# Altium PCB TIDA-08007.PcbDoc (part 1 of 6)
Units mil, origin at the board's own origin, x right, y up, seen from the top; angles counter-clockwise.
Board outline 4212.6 x 2047.24 mil, 10 copper layers (Top Layer, GND 1, Signal Layer 1, GND 2, Split PWR 1, Split PWR 2, GND 3, Signal Layer 2, GND 4, Bottom Layer), stack 66.4 mil thick; 291 components, 178 nets, 1281 pads, 873 vias.
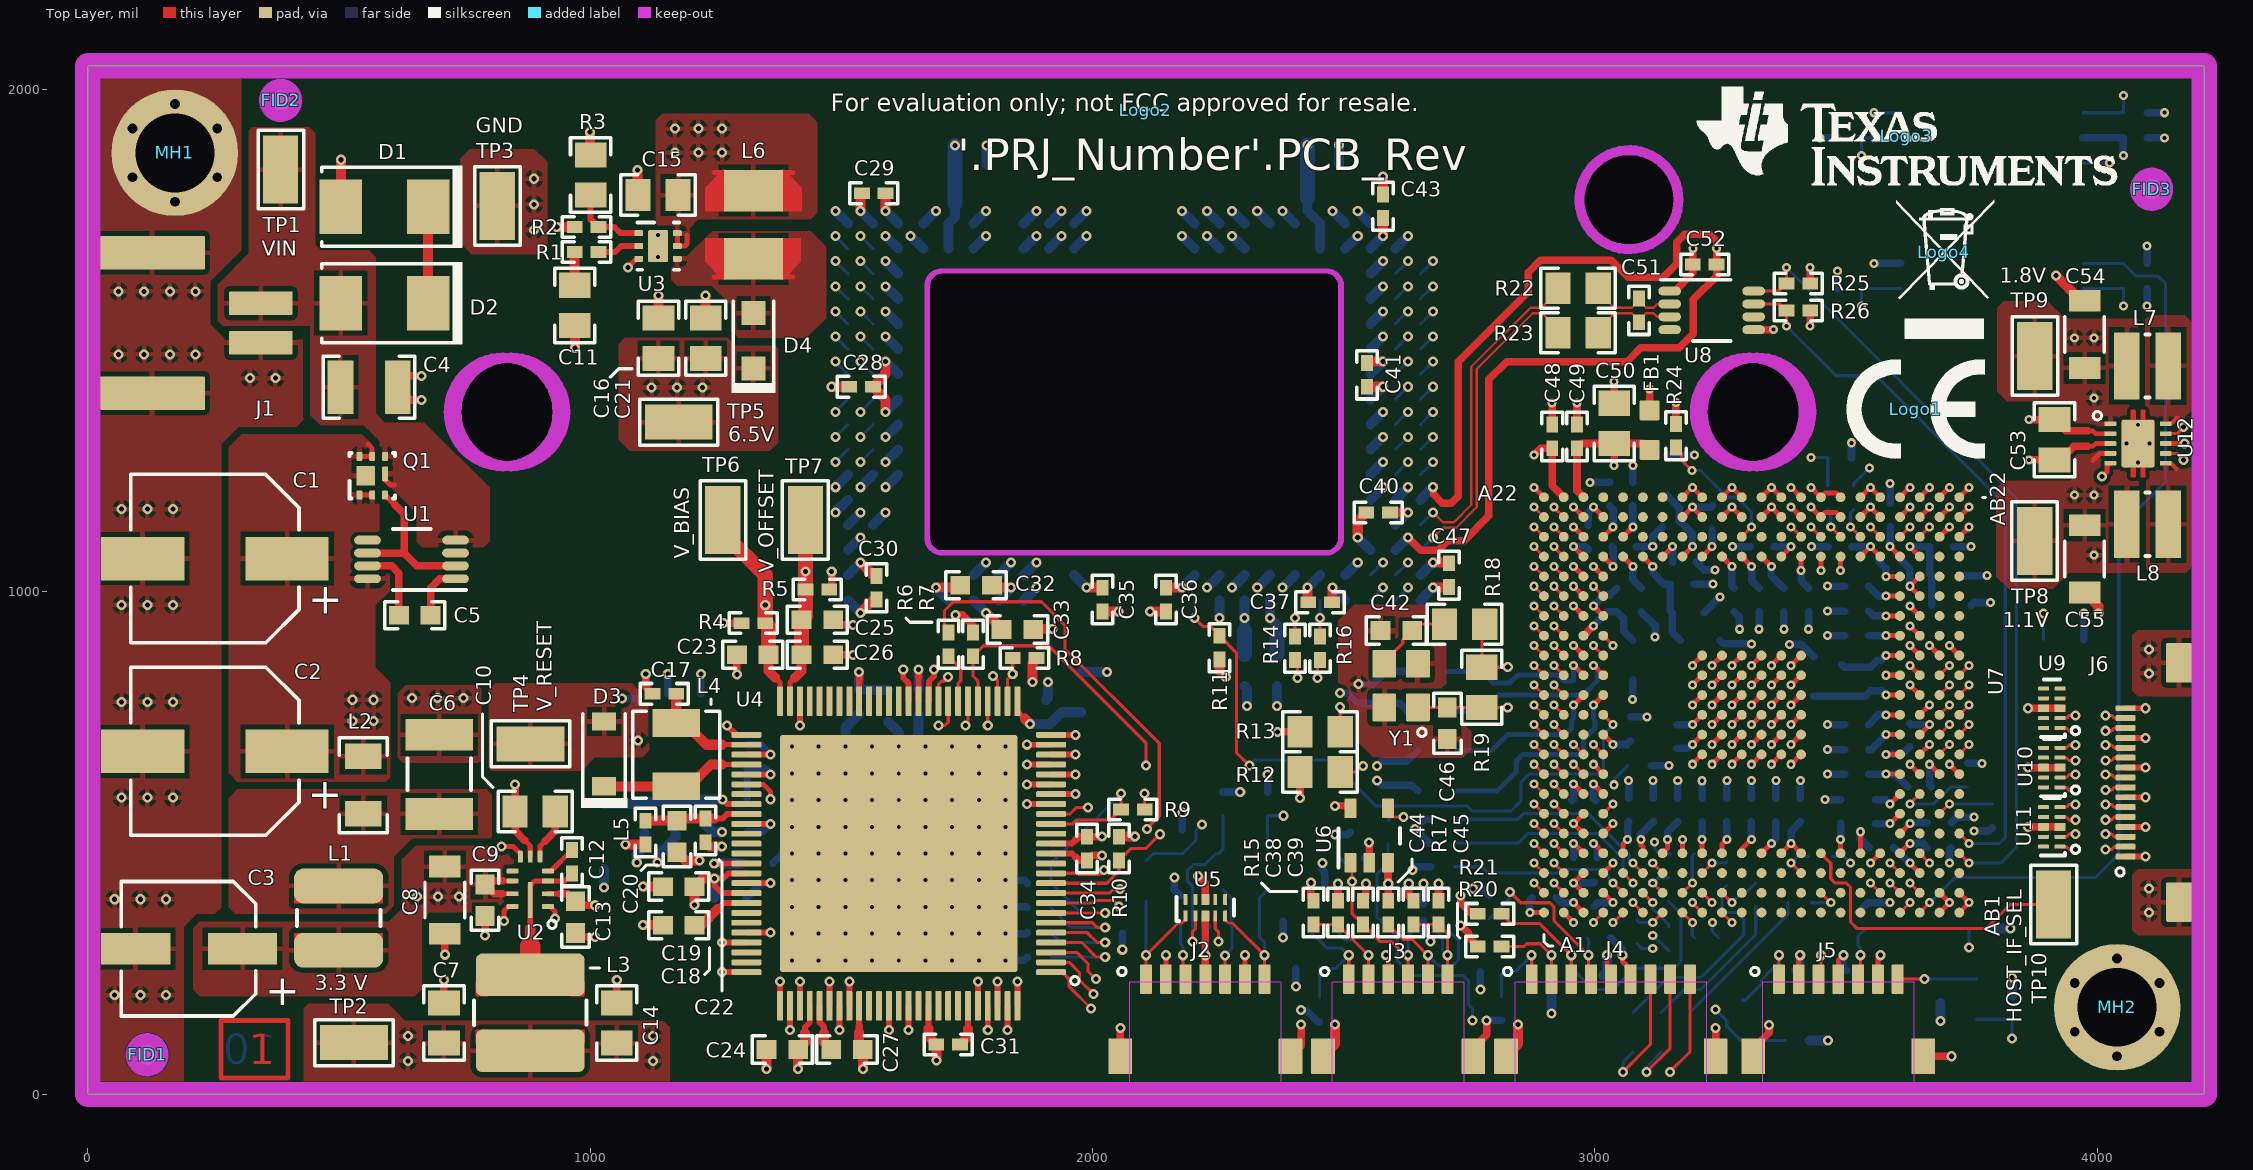
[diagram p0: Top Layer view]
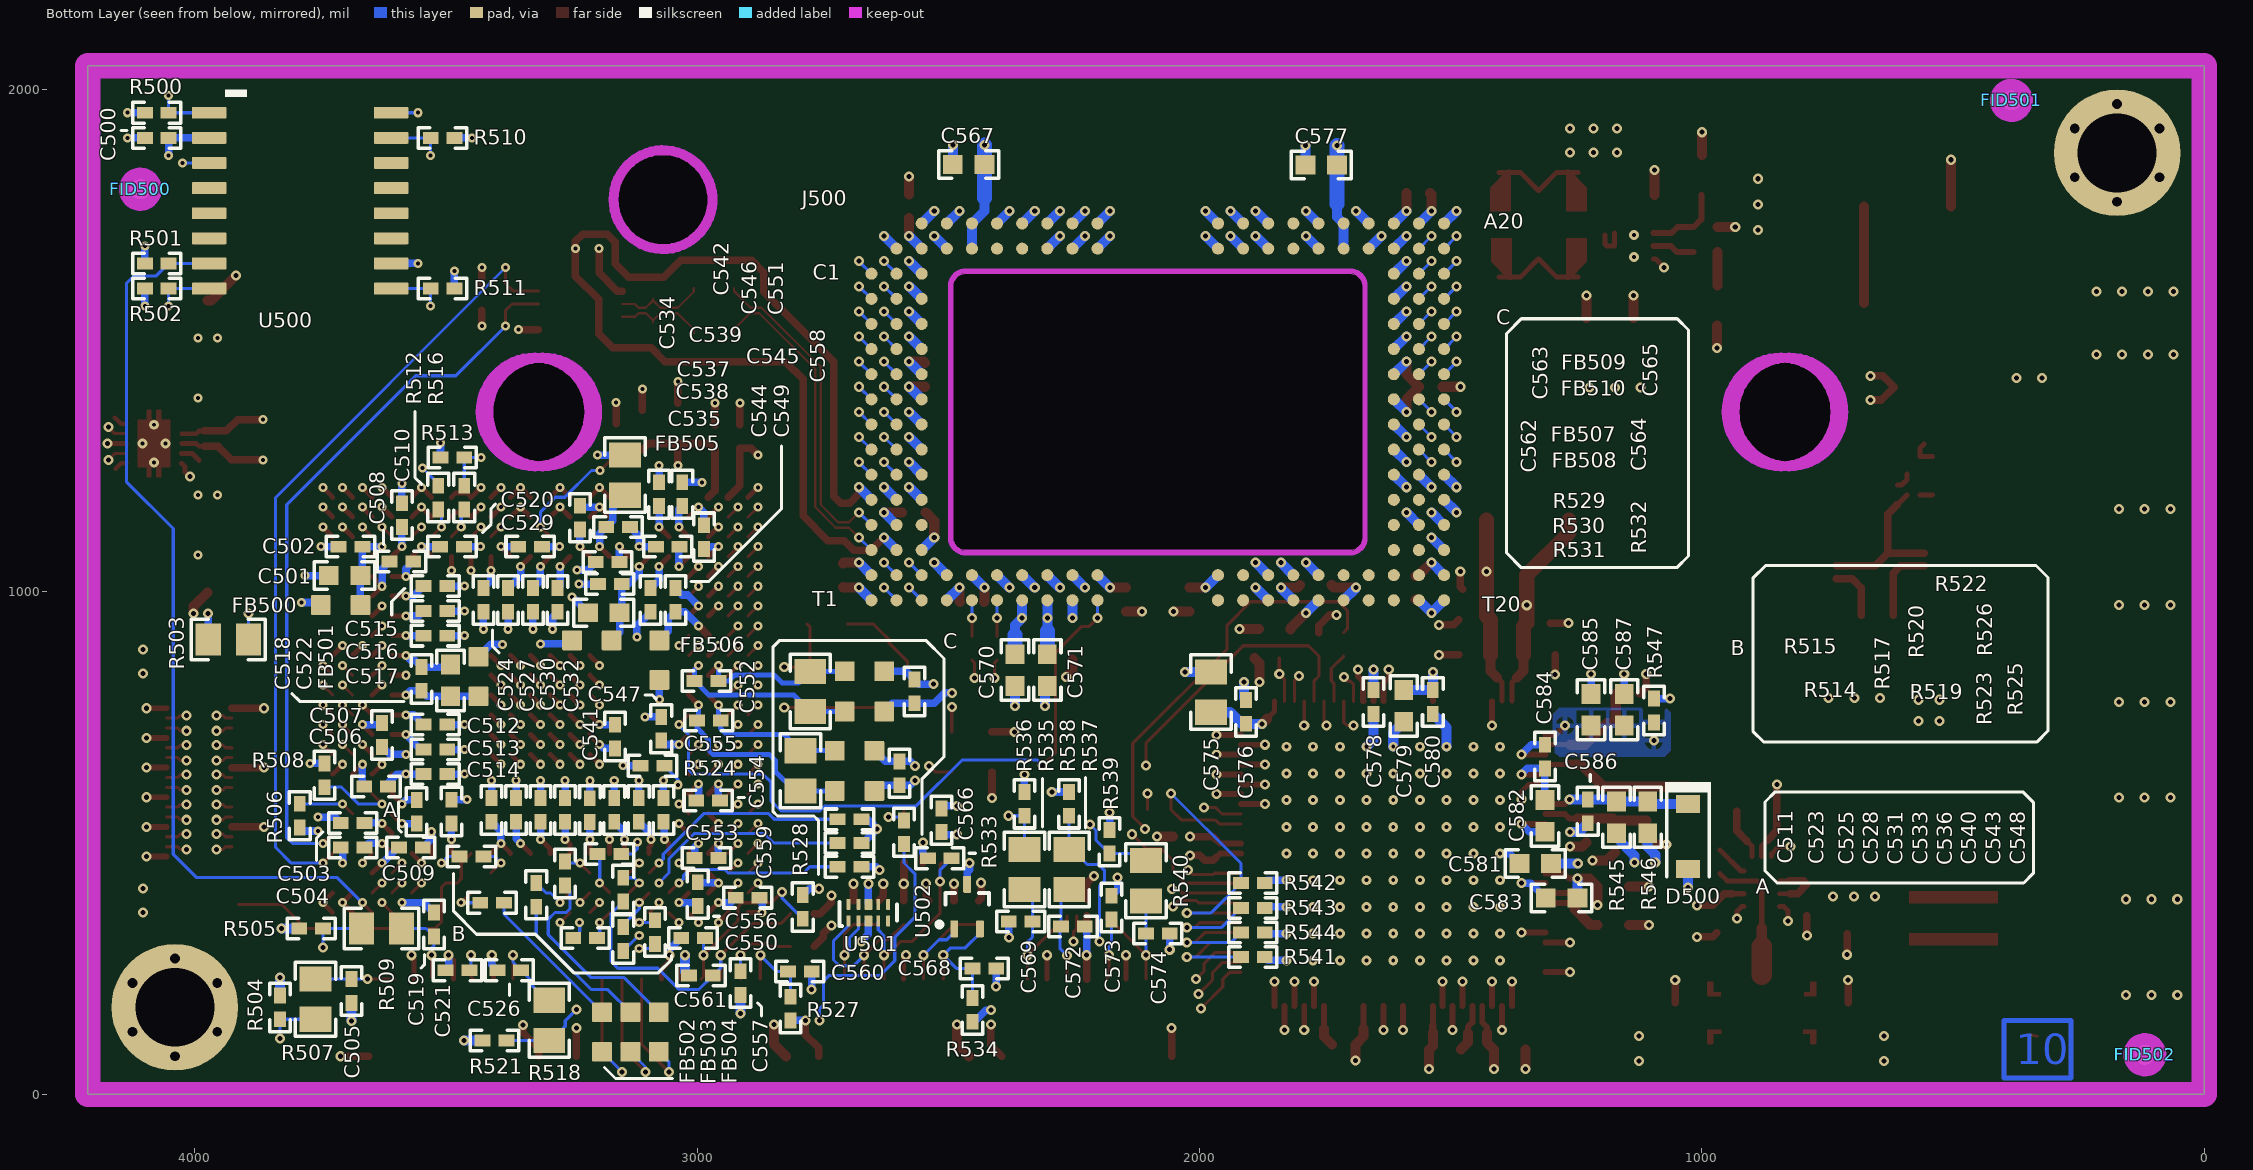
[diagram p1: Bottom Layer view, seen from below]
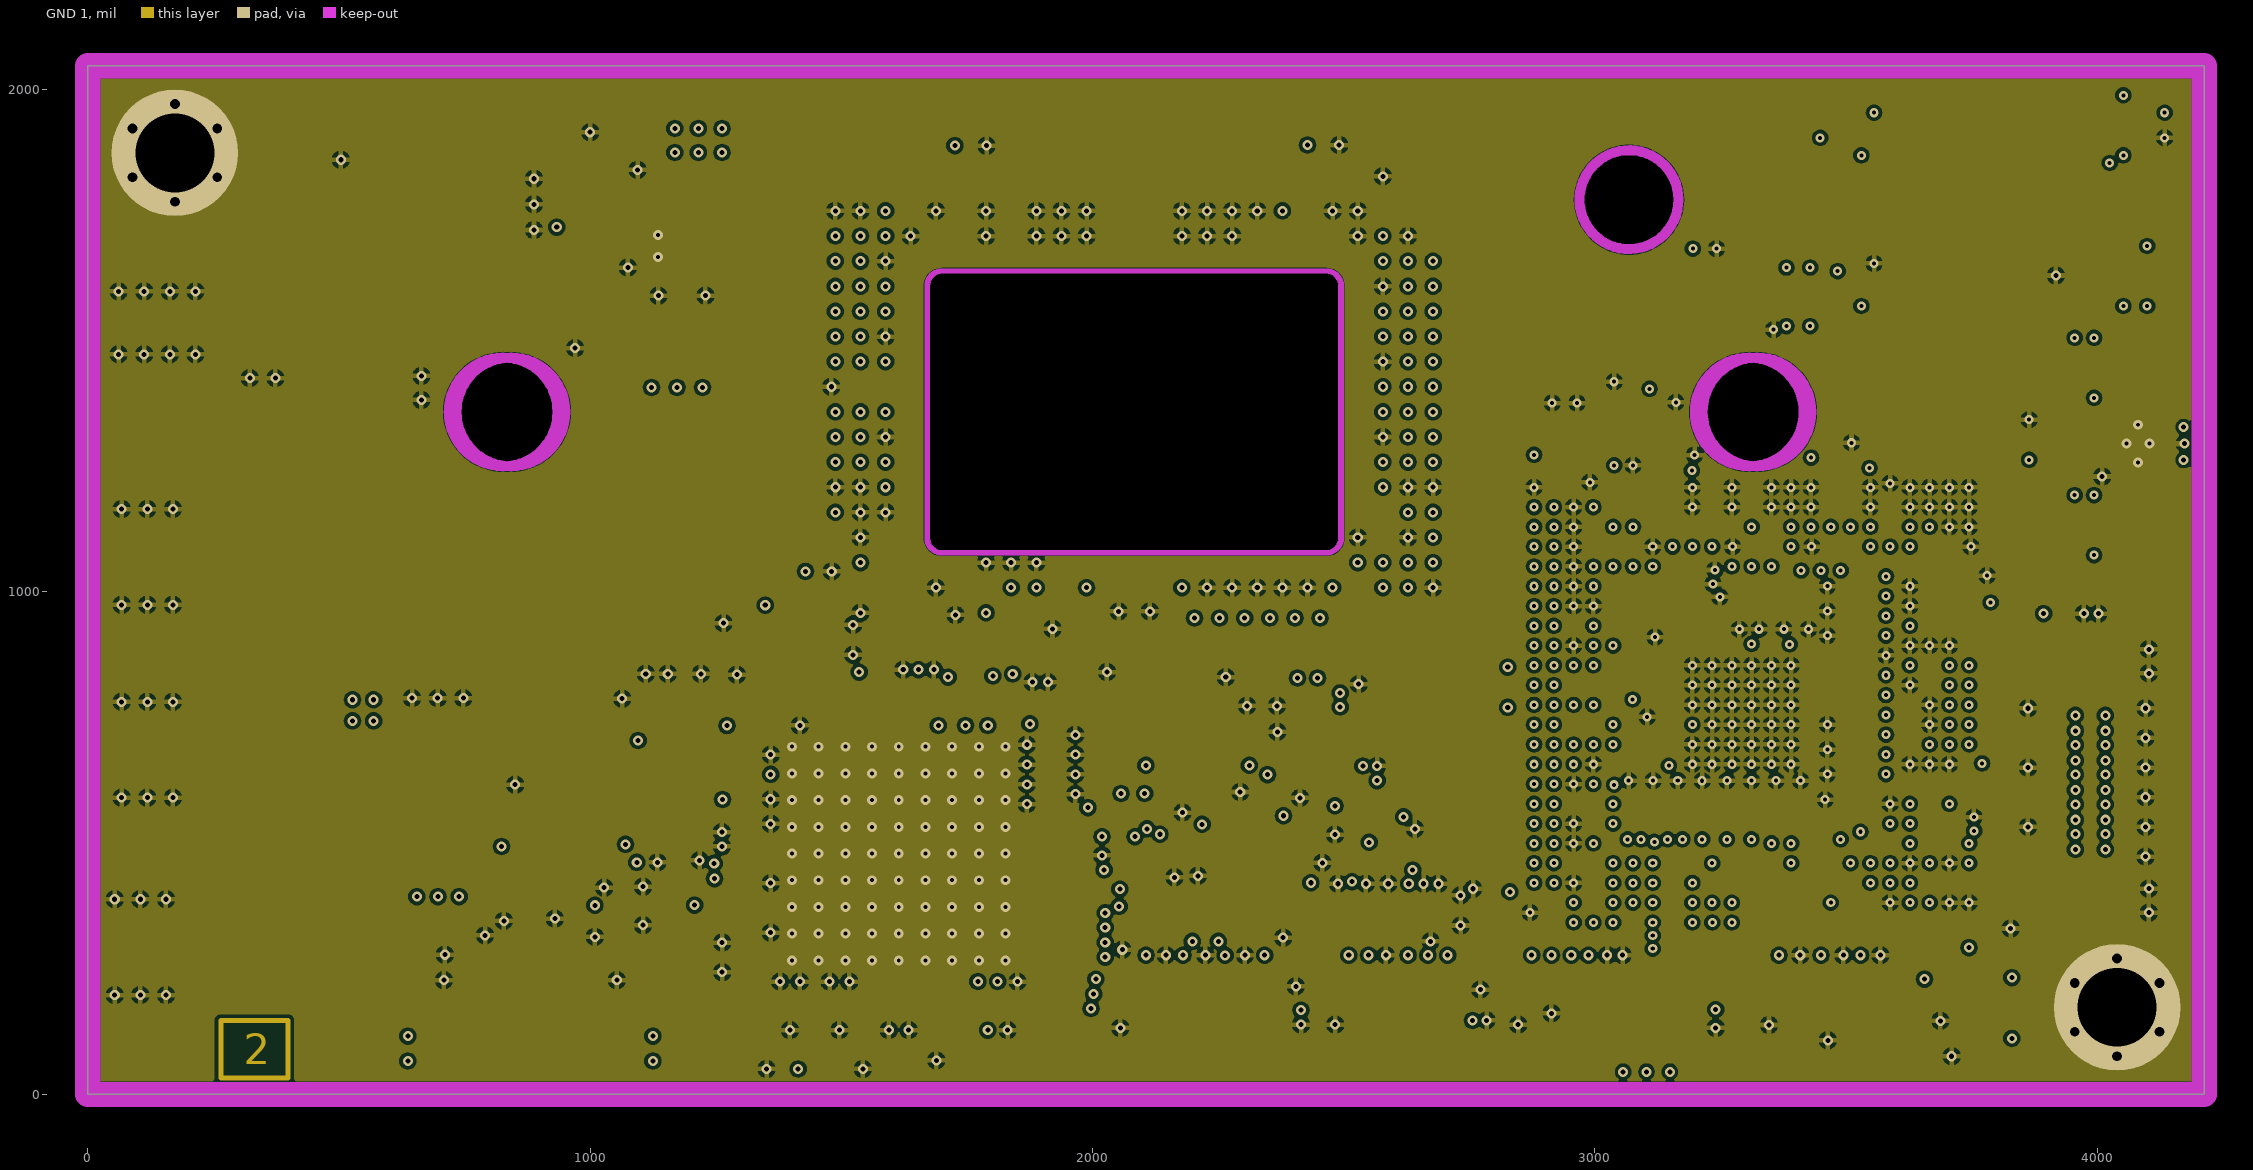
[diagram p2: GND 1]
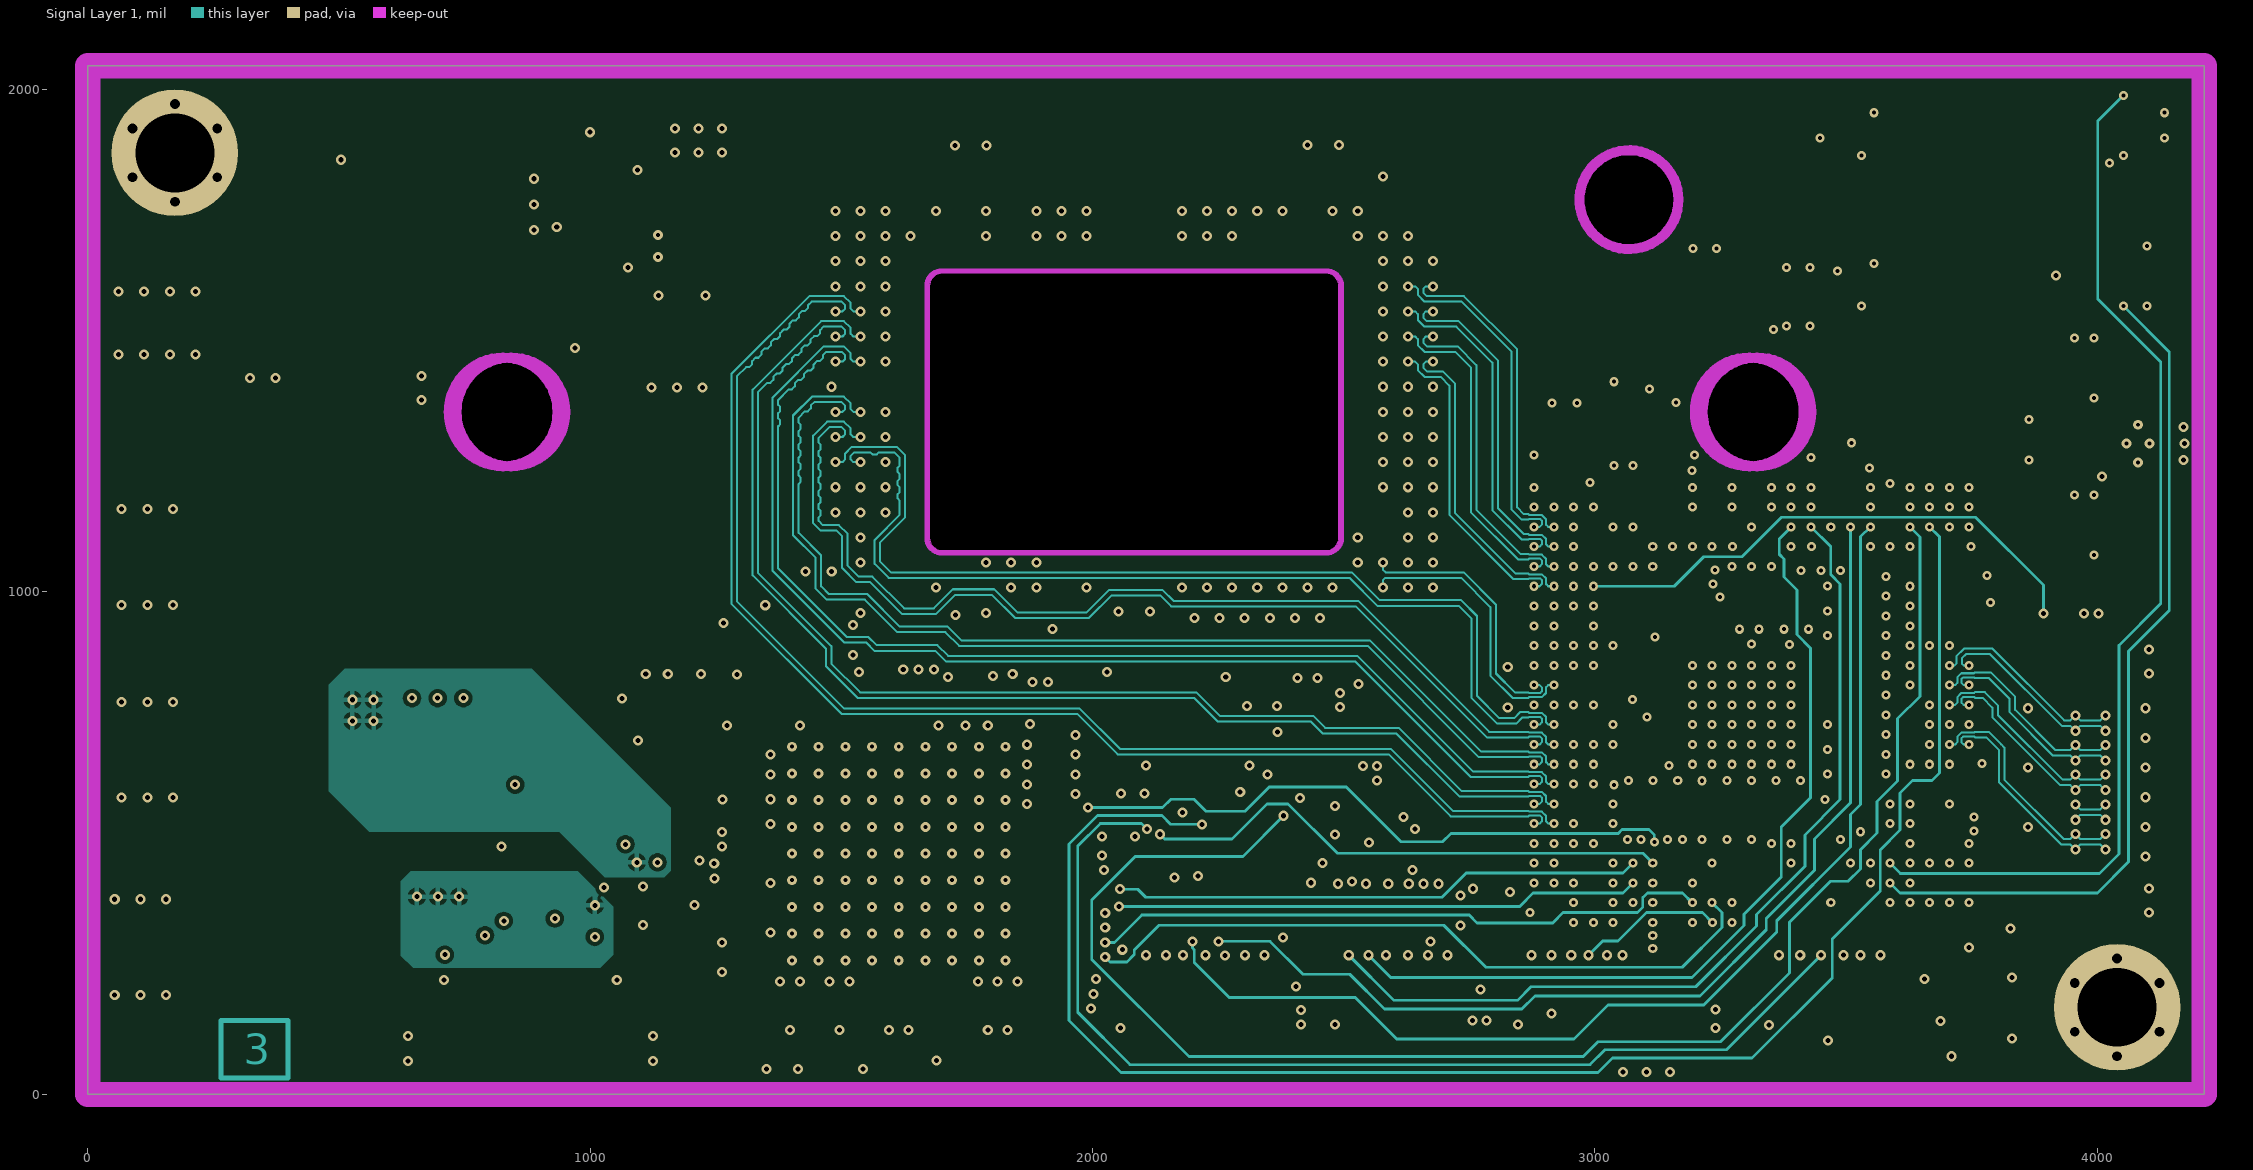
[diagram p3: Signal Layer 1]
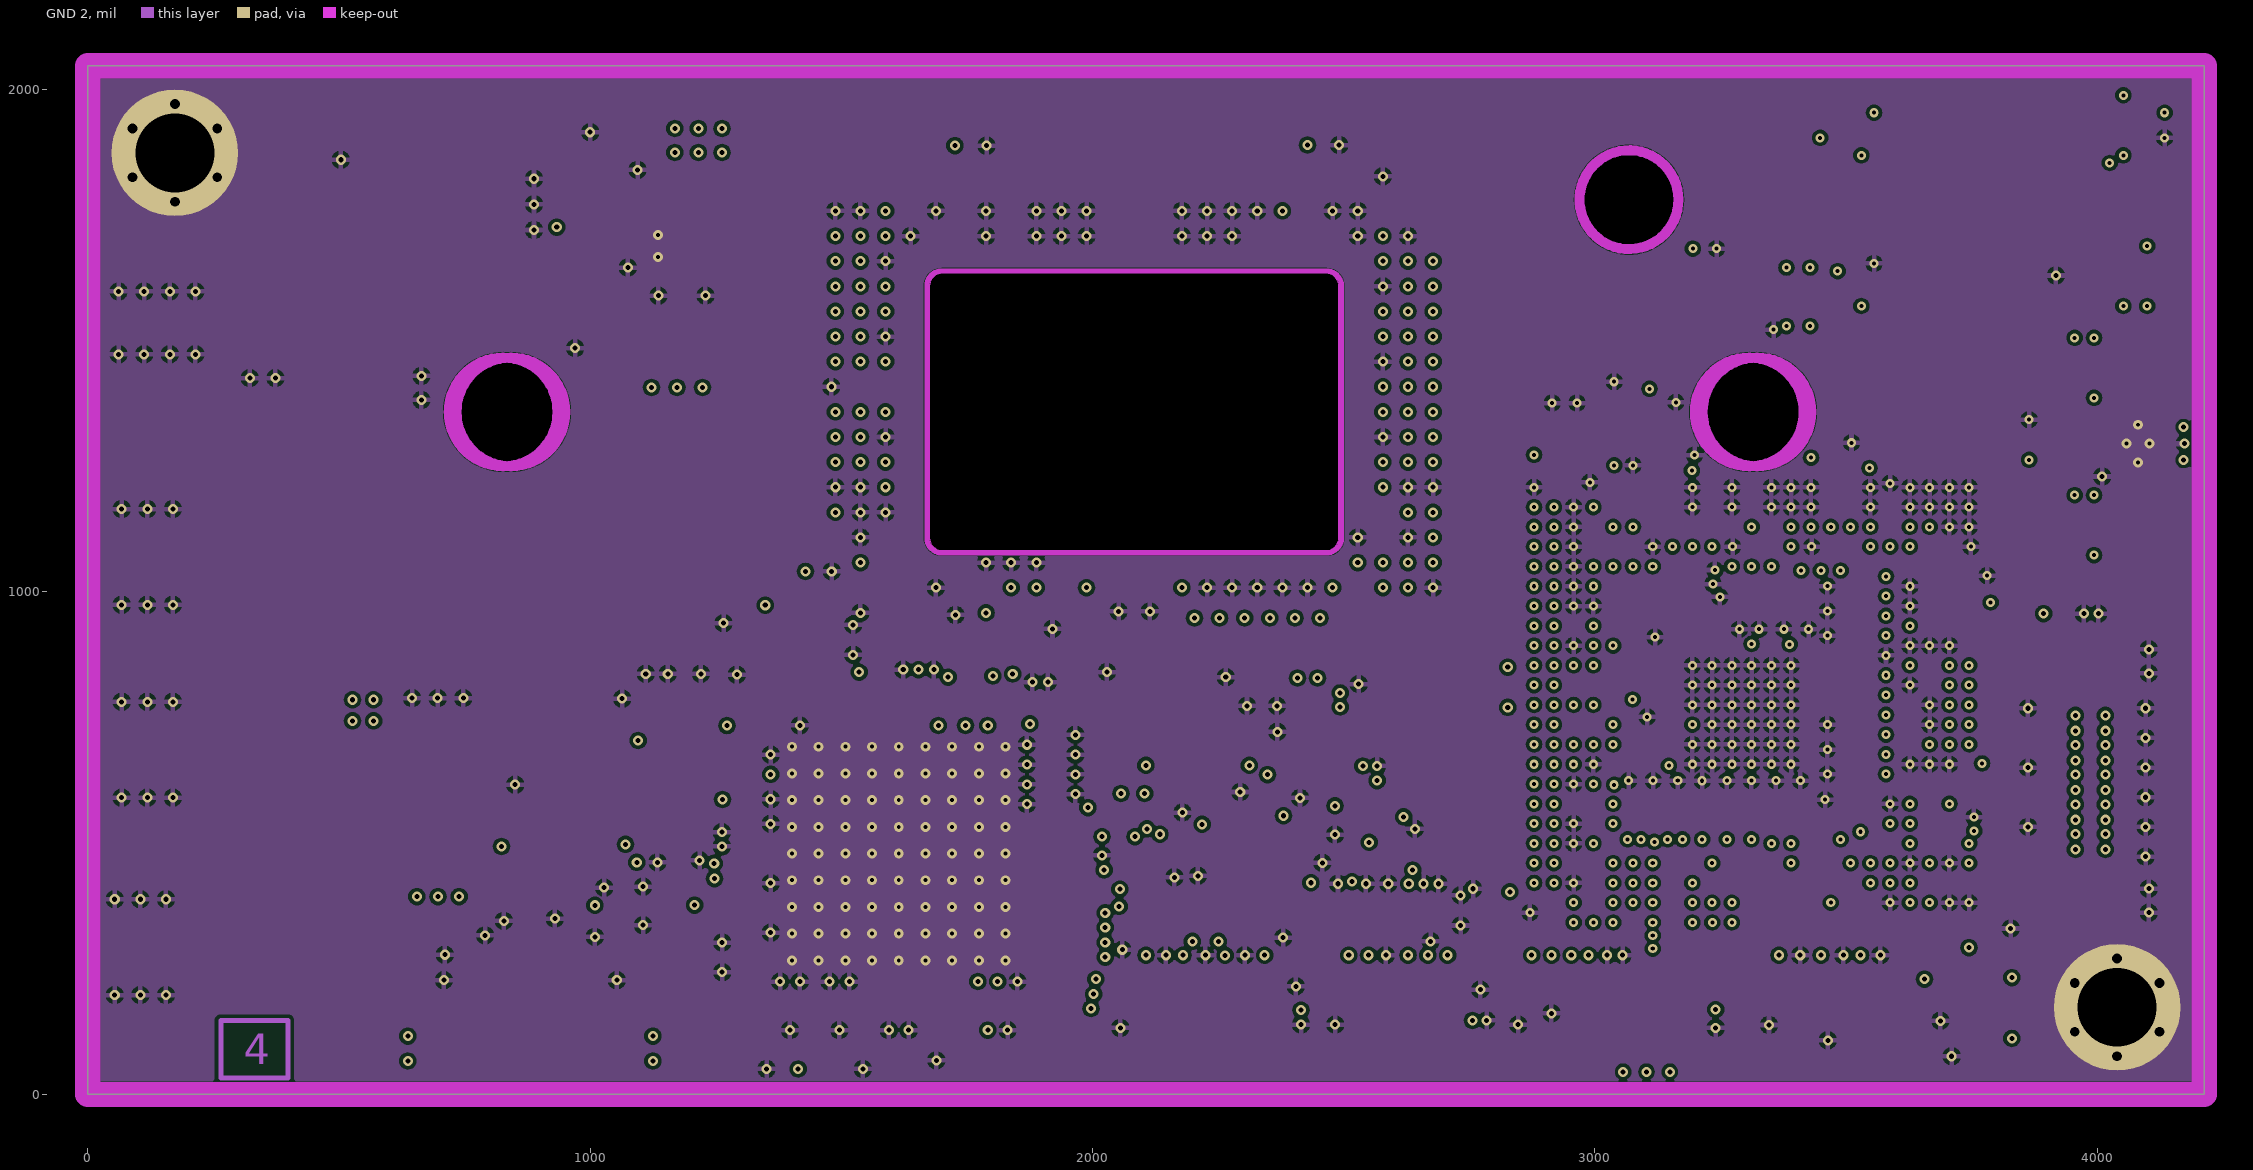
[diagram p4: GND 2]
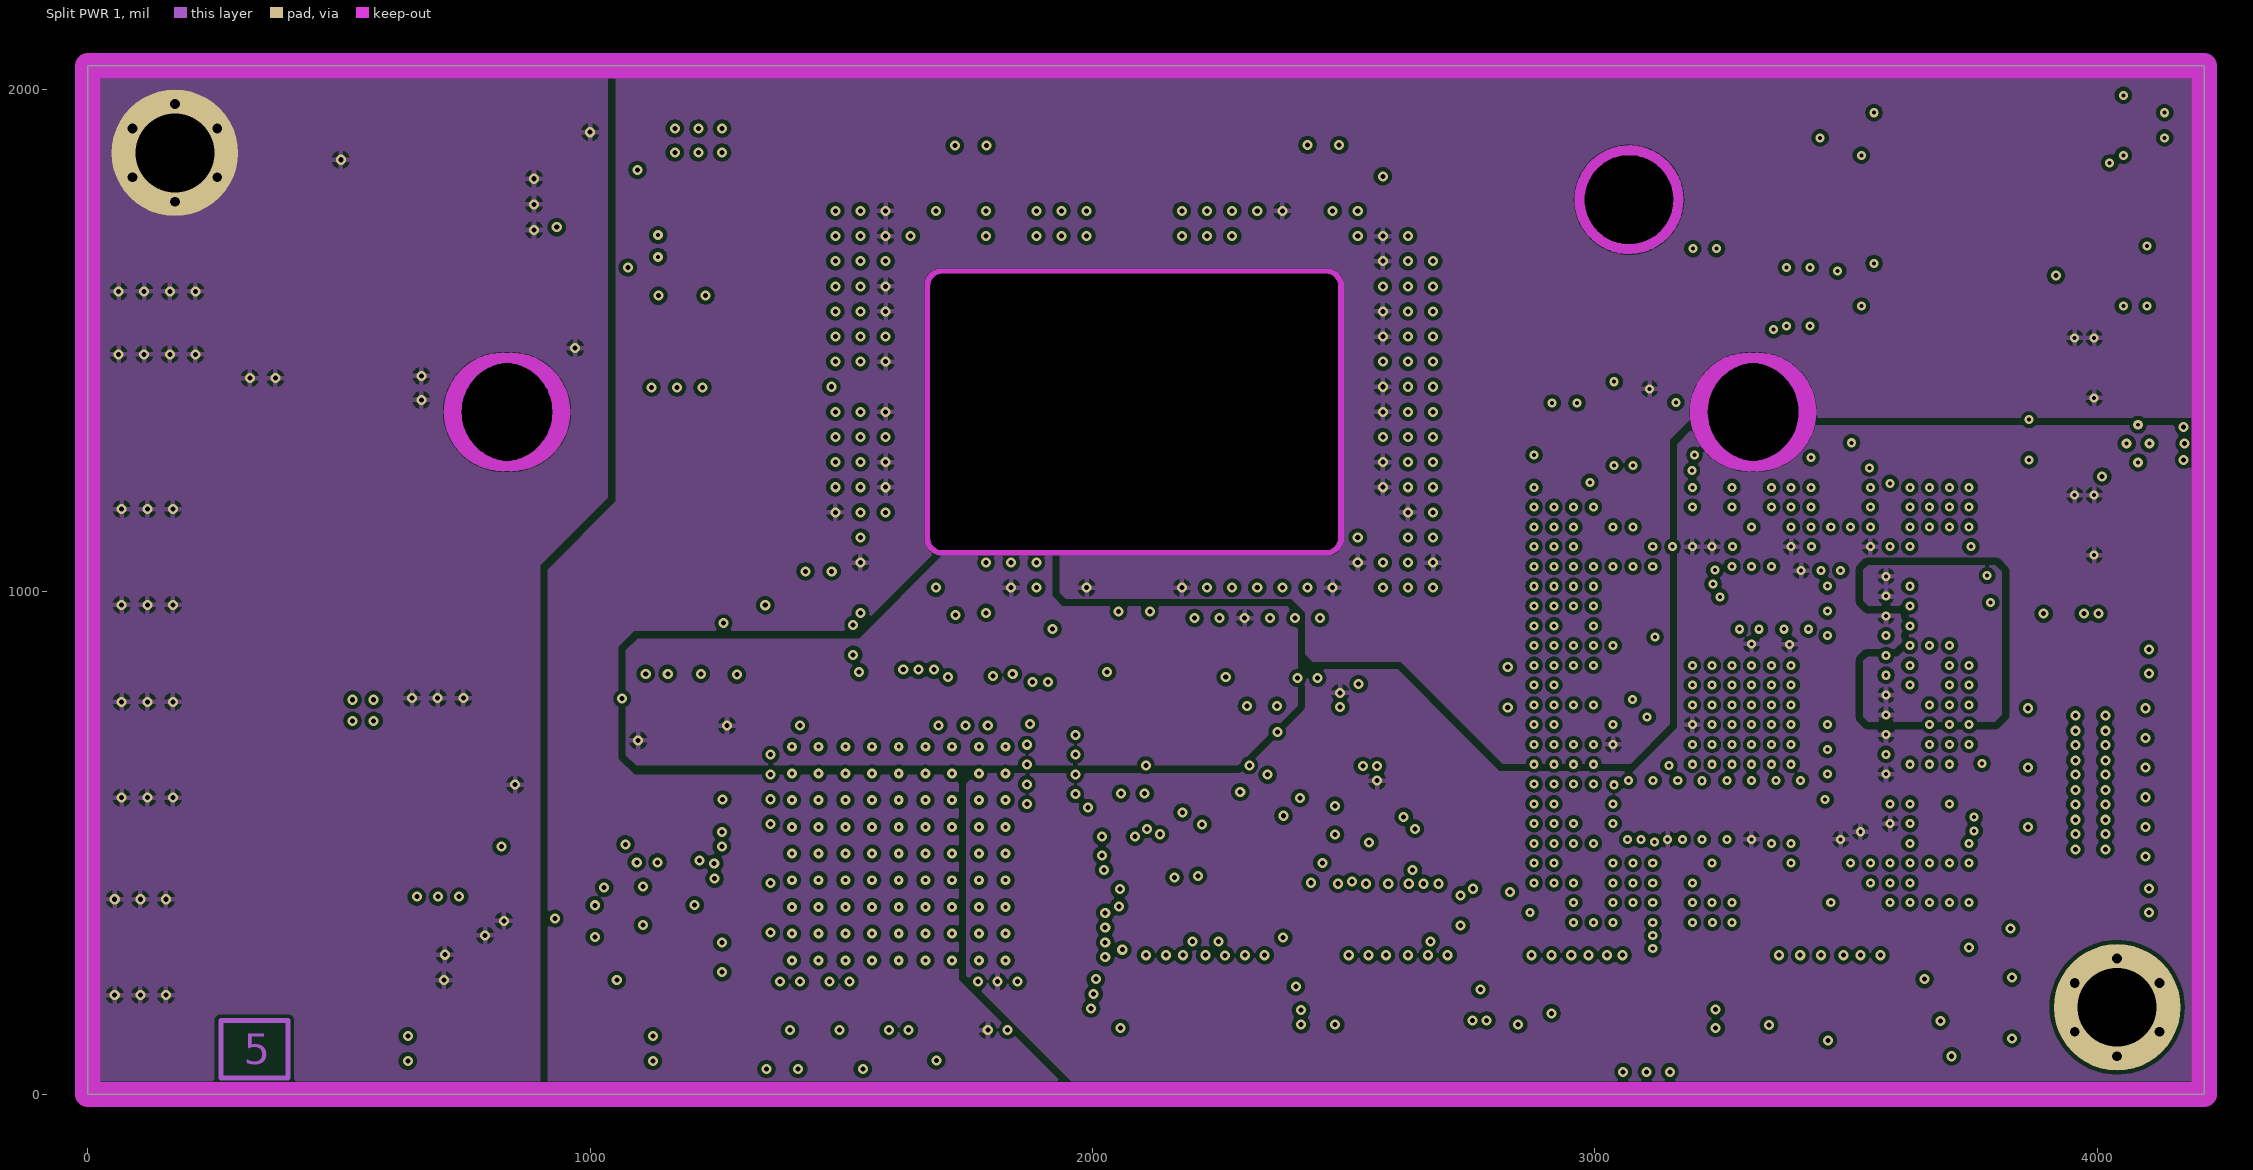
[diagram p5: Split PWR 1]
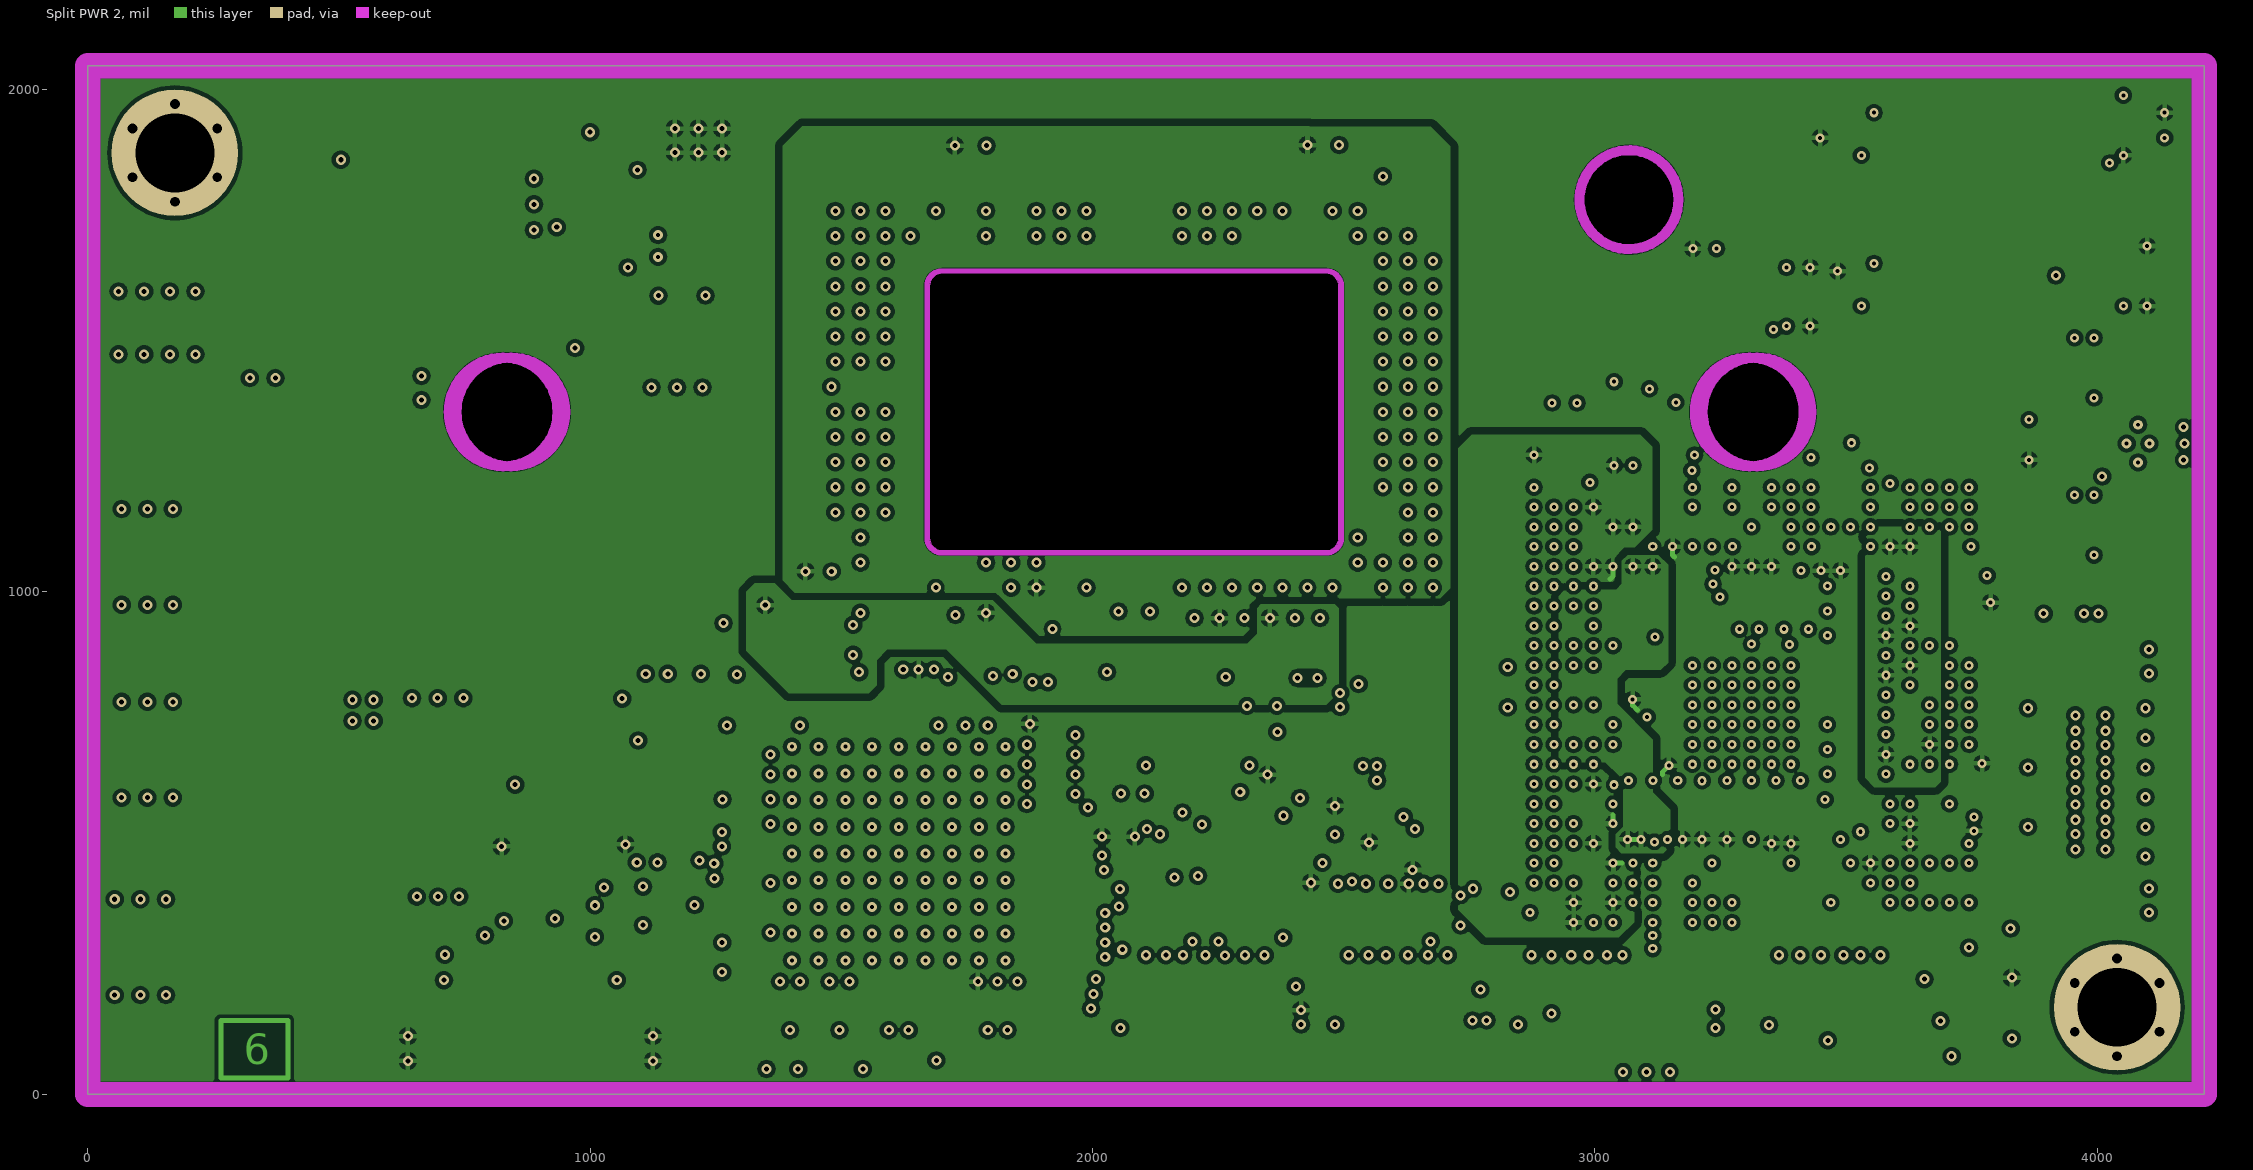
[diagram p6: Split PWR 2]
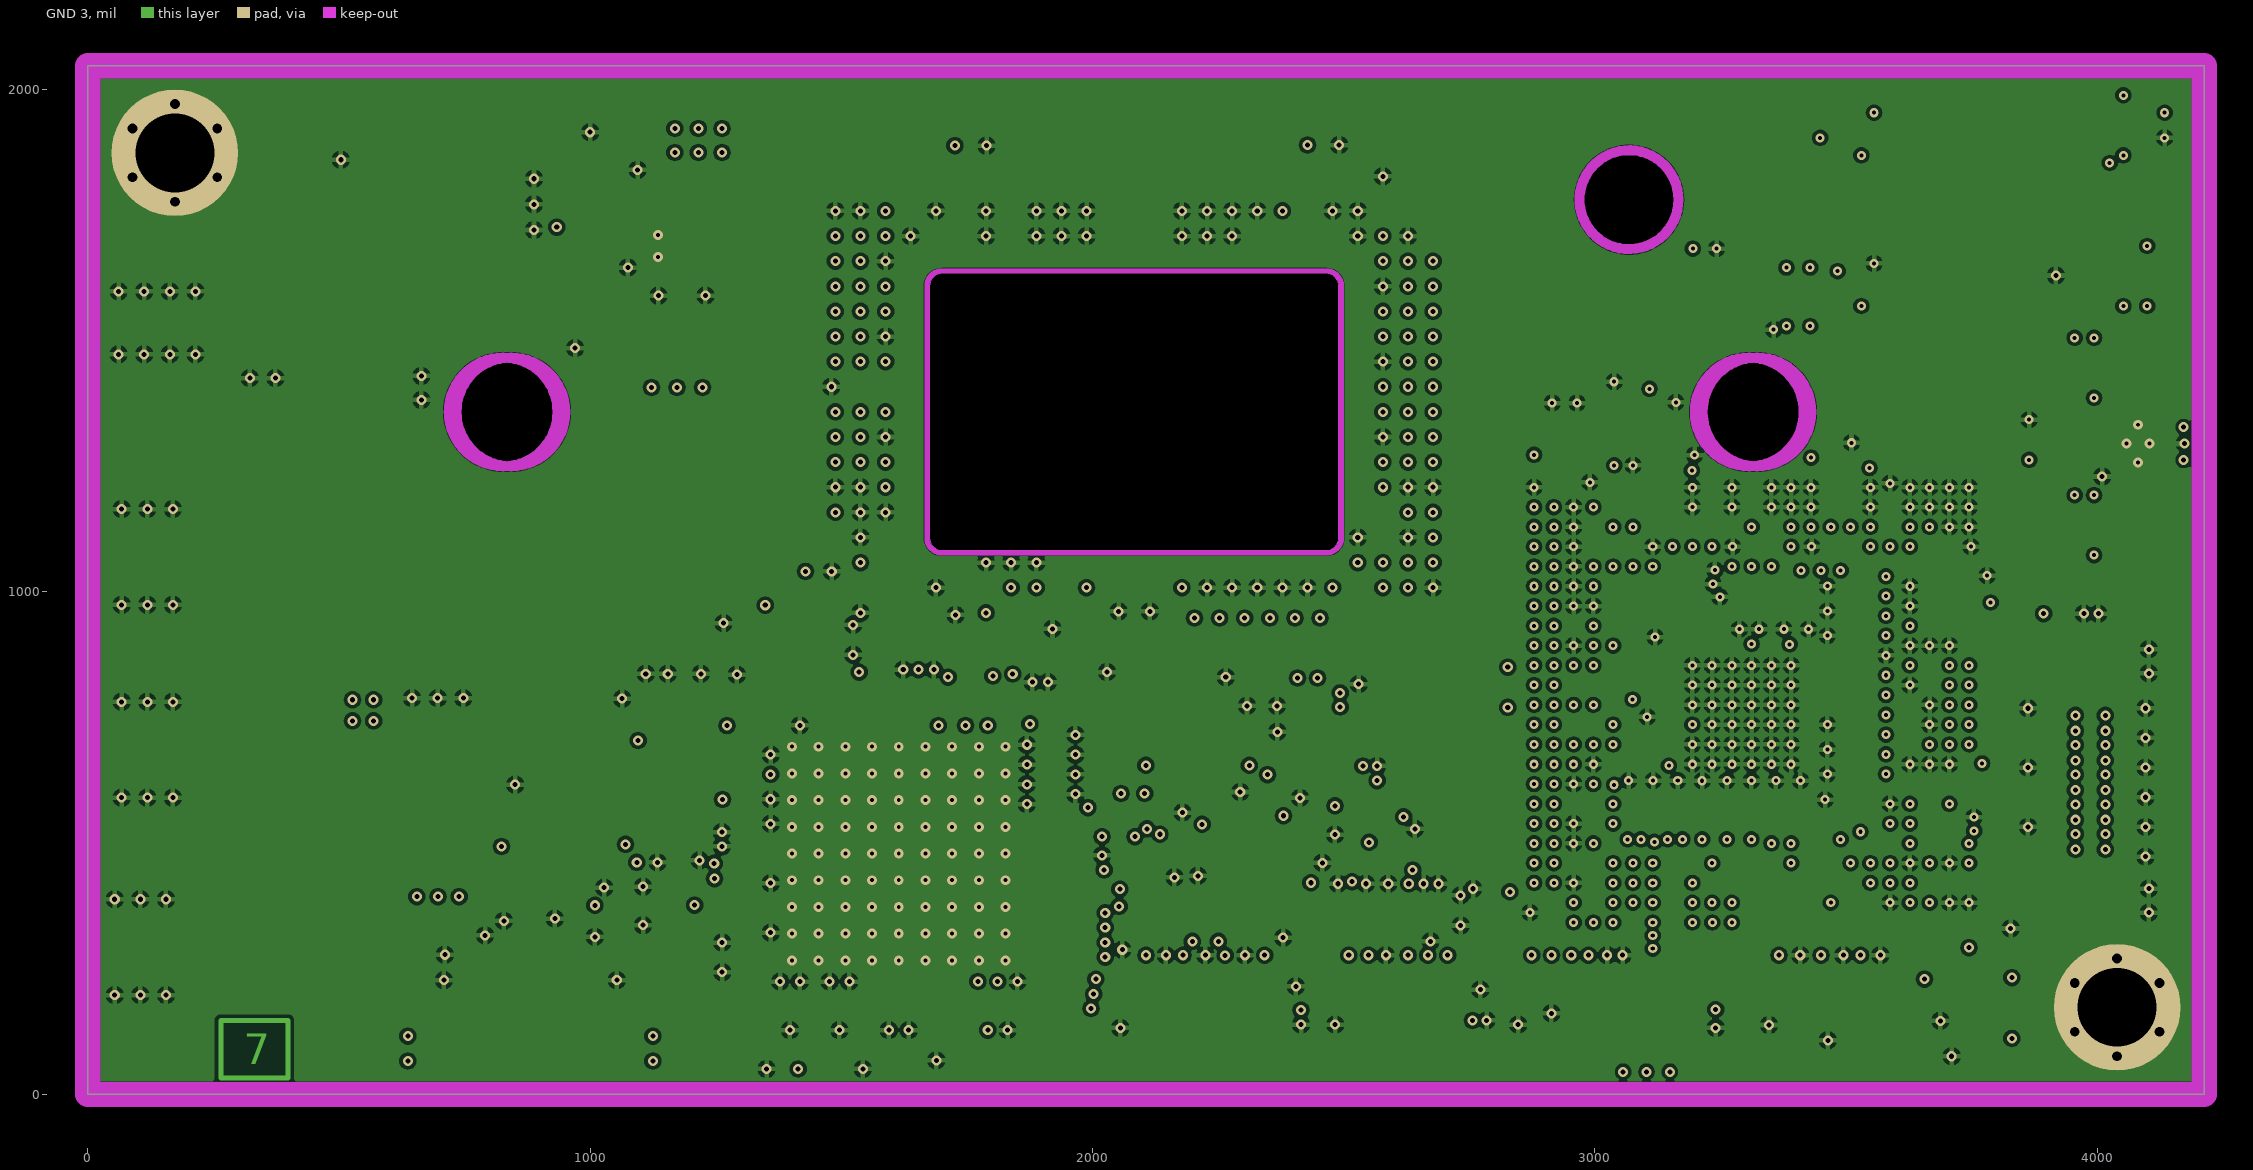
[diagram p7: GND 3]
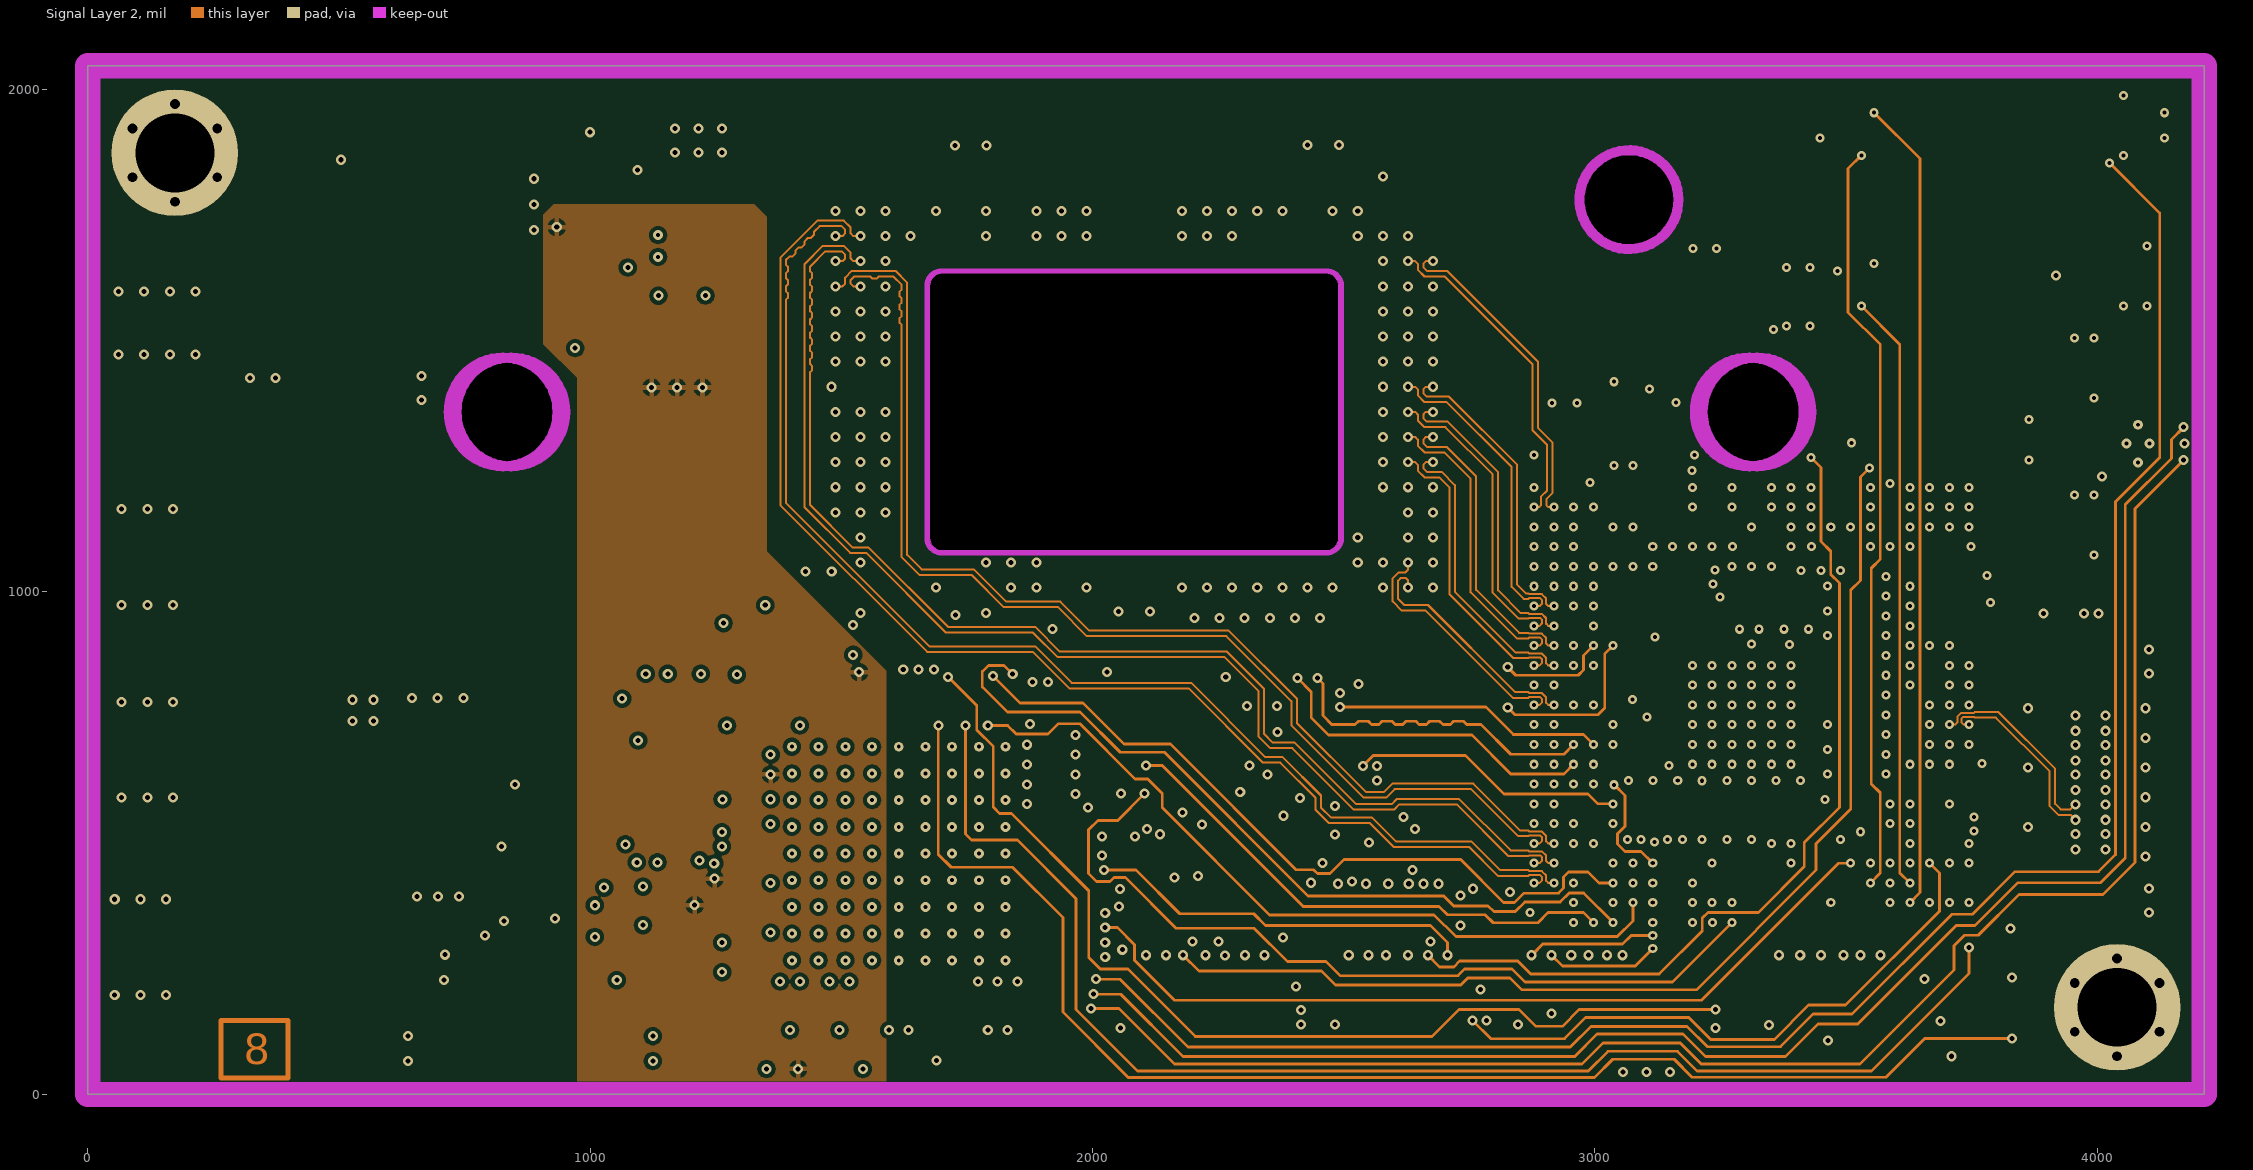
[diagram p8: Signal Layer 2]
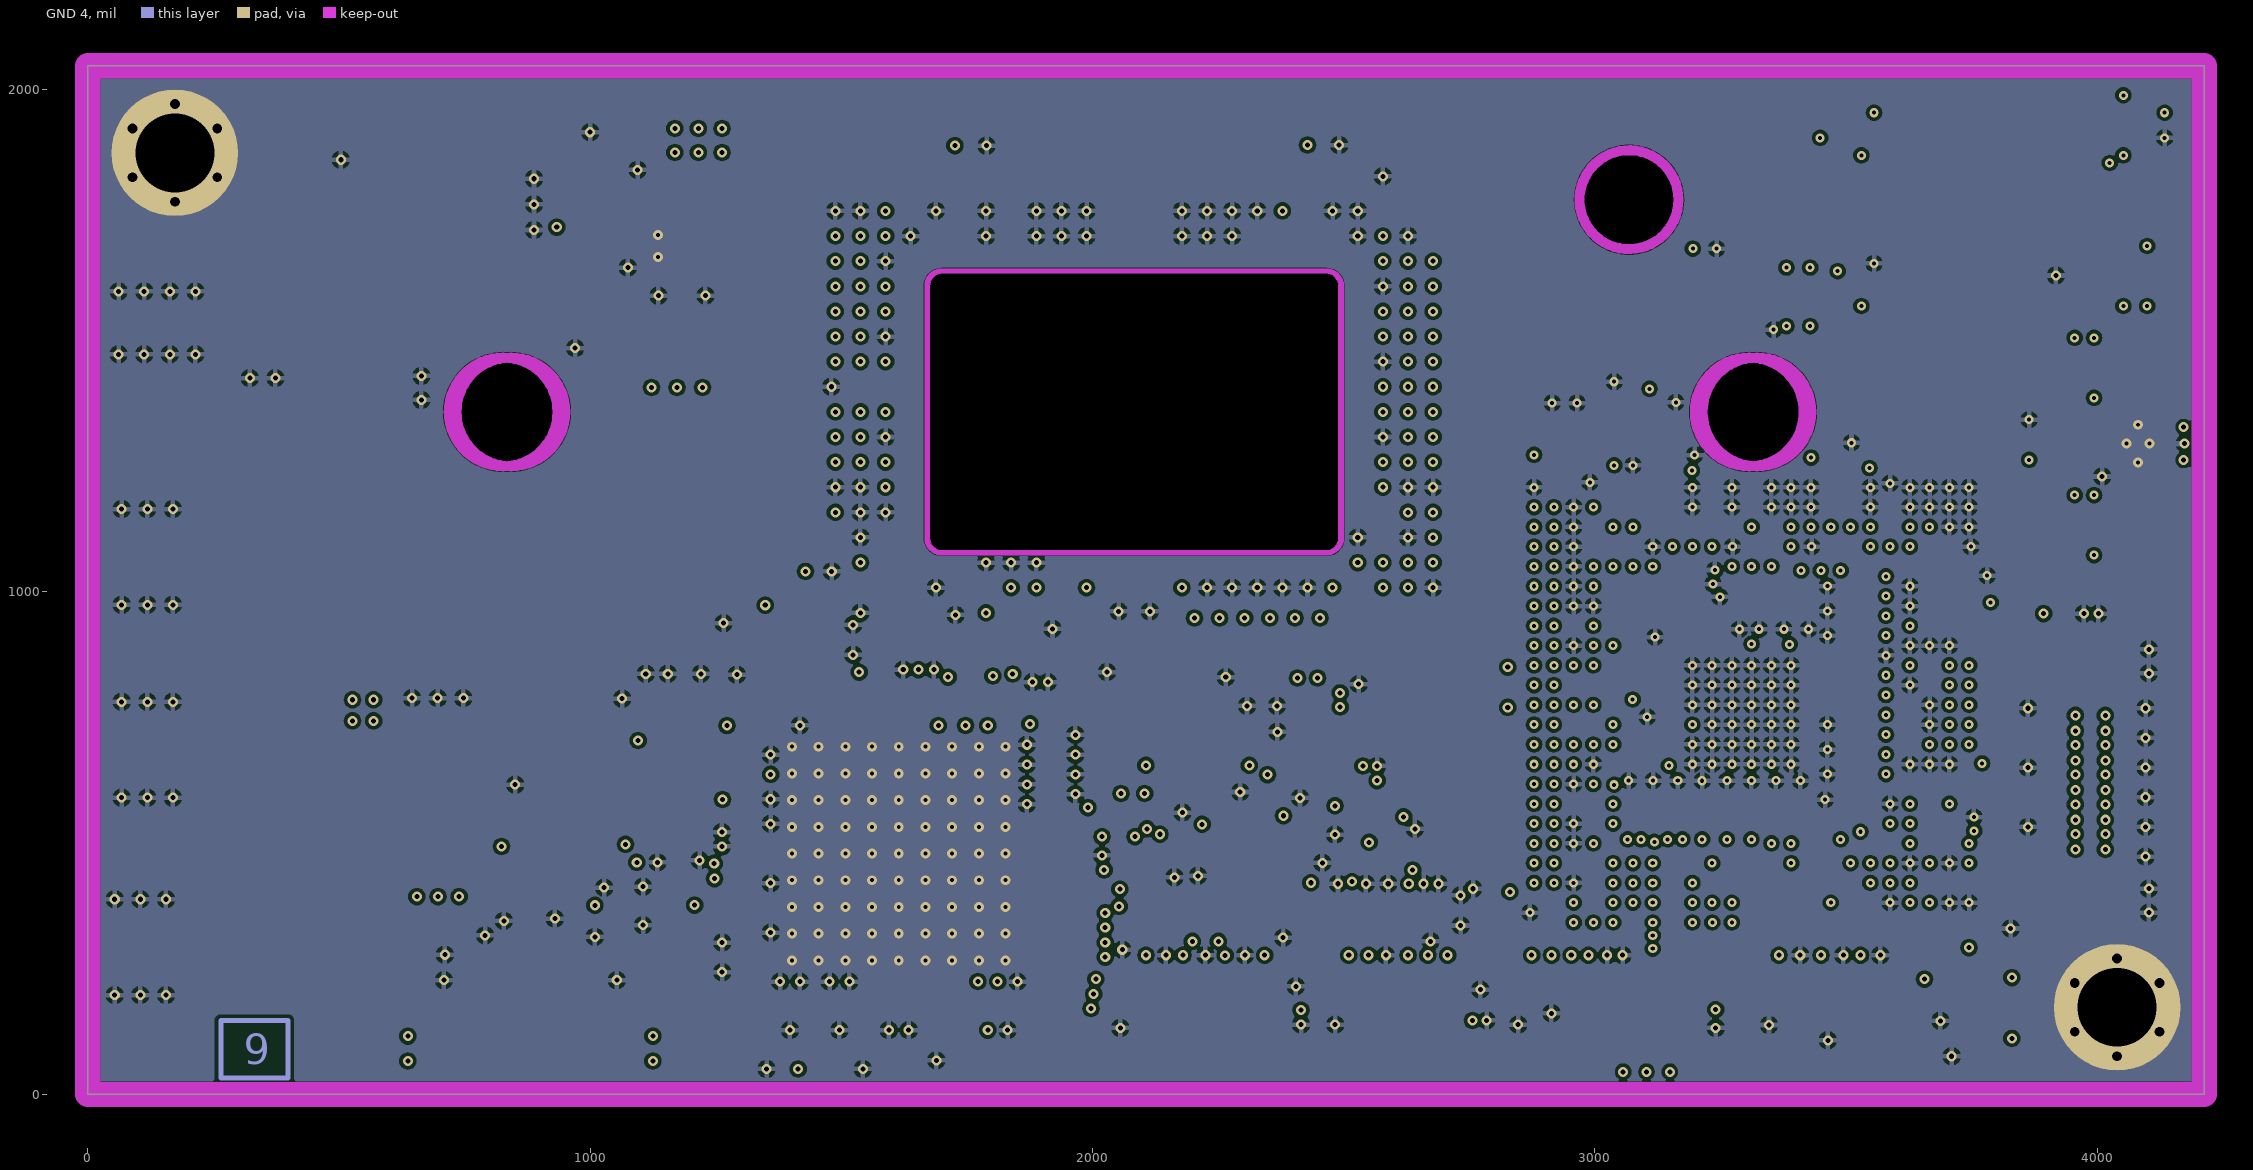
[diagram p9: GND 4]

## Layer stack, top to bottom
Top Solder: solder mask 0.8, Solder Resist, Dk 3.3
Top Layer: signal copper 1.6
Dielectric 1: prepreg 4, FR-4, Dk 4.2
GND 1: signal copper 1.4
Dielectric 2: core 8, FR-4, Dk 4.2
Signal Layer 1: signal copper 1.4
Dielectric 3: dielectric 8, FR-4, Dk 4.2
GND 2: signal copper 1.4
Dielectric 4: prepreg 4, FR-4, Dk 4.2
Split PWR 1: signal copper 1.4
Dielectric 5: core 4, FR-4, Dk 4.2
Split PWR 2: signal copper 1.4
Dielectric 6: prepreg 4, FR-4, Dk 4.2
GND 3: signal copper 1.4
Dielectric 7: dielectric 8, FR-4, Dk 4.2
Signal Layer 2: signal copper 1.4
Dielectric 8: core 8, FR-4, Dk 4.2
GND 4: signal copper 1.4
Dielectric 9: prepreg 4, FR-4, Dk 4.2
Bottom Layer: signal copper 1.6
Bottom Solder: solder mask 0.8, Solder Resist, Dk 3.3

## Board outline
0,0 0,2047.24 4212.6,2047.24 4212.6,0
cut-out: 3198.82,1358.27 ccw(c3307.09,1358.27) 3307.09,1250 ccw(c3307.09,1358.27) 3415.35,1358.27 ccw(c3307.09,1358.27) 3307.09,1466.54 ccw(c3307.09,1358.27)
cut-out: 826.77,1250 cw(c826.77,1358.27) 718.5,1358.27 cw(c826.77,1358.27) 826.77,1466.54 cw(c826.77,1358.27) 935.04,1358.27 cw(c826.77,1358.27)
cut-out: 842.13,1250 cw(c842.13,1358.27) 733.86,1358.27 cw(c842.13,1358.27) 842.13,1466.54 cw(c842.13,1358.27) 950.39,1358.27 cw(c842.13,1358.27)
cut-out: 3214.17,1358.27 ccw(c3322.44,1358.27) 3322.44,1250 ccw(c3322.44,1358.27) 3430.71,1358.27 ccw(c3322.44,1358.27) 3322.44,1466.54 ccw(c3322.44,1358.27)
cut-out: 2969.29,1780.71 ccw(c3067.72,1780.71) 3067.72,1682.28 ccw(c3067.72,1780.71) 3166.14,1780.71 ccw(c3067.72,1780.71) 3067.72,1879.13 ccw(c3067.72,1780.71)
cut-out: 1675.19,1608.54 1675.19,1108 1675.2,1107.99 ccw(c1700.51,1107.99) 1700.51,1082.68 2464.84,1082.68 ccw(c2464.84,1107.99) 2490.16,1107.99 2490.16,1608.54 ccw(c2464.84,1608.54) 2464.84,1633.86 1700.51,1633.86 ccw(c1700.51,1608.54) 1675.2,1608.54

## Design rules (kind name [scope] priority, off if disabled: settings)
AcuteAngle [All] p1: minimum=4.50000000000000E+0001 checktracksonly=FALSE
AssemblyTestPointUsage [All] p1: valid=2
Clearance "Clearance_Avoid fall" [isvia vs InLayerClass('GND') and InPolygon] p1: gap=7 ignorepadtopadclearanceinfootprint=TRUE
Clearance Clearance_Temp [(InNet('TEMP_P') or InNet('TMP411_P')) and IsTrack vs (InNet('TEMP_N') or InNet('TMP411_N')) and IsTrack] p2: gap=6.5 ignorepadtopadclearanceinfootprint=TRUE
Clearance "Clearance_Comp Edge" [IsKeepOut and IsTrack vs (HasFootprint('FP-505110-1692_CONN_SMT_12MM7_5MM25-MFG') or HasFootprint('FP-502352-0200_HDR2-MFG')) and ispad] p3: gap=0 ignorepadtopadclearanceinfootprint=TRUE
Clearance Clearance_U2 [WithinRoom('Room_U2') and (IsPad or IsVia or istrack) vs istrack] p4: gap=4 ignorepadtopadclearanceinfootprint=TRUE
Clearance Clearance_Fid [HasFootprint('Fiducial10-20') and ispad vs HasFootprint('Fiducial10-20') and IsArc and IsKeepOut] p5: gap=0 ignorepadtopadclearanceinfootprint=TRUE
Clearance Clearance_Keepouts [IsKeepOut] p6: gap=1 ignorepadtopadclearanceinfootprint=FALSE
Clearance "Clearance_Poly 2 Poly" [InPolygon vs InPolygon] p7: gap=15 ignorepadtopadclearanceinfootprint=TRUE
Clearance Clearance_Poly [InPolygon] p8: gap=8 ignorepadtopadclearanceinfootprint=TRUE
Clearance [All] p9: gap=7 ignorepadtopadclearanceinfootprint=TRUE
DiffPairsRouting [All] p1: maxlimit=100 minlimit=6.5 mostfreqgap=10 toplayer_maxgap=6.5 toplayer_prefgap=6.5 toplayer_minwidth=4.5 toplayer_maxwidth=6.2 toplayer_prefwidth=4.5 midlayer1_mingap=10 midlayer1_minwidth=7 midlayer1_maxwidth=7 midlayer1_prefwidth=7 midlayer2_mingap=10 midlayer2_minwidth=7 midlayer2_maxwidth=7 midlayer2_prefwidth=7 midlayer3_mingap=7 midlayer3_maxgap=7 midlayer3_prefgap=7 midlayer3_minwidth=4 midlayer3_maxwidth=4 midlayer3_prefwidth=4 midlayer4_mingap=10 midlayer4_minwidth=7 midlayer4_maxwidth=7 midlayer4_prefwidth=7 midlayer5_mingap=10 midlayer5_minwidth=7 midlayer5_maxwidth=7 midlayer5_prefwidth=7 midlayer6_mingap=7 midlayer6_maxgap=7 midlayer6_prefgap=7 midlayer6_minwidth=4 midlayer6_maxwidth=4 midlayer6_prefwidth=4 midlayer7_mingap=10 midlayer7_minwidth=7 midlayer7_maxwidth=7 midlayer7_prefwidth=7 midlayer8_mingap=10 midlayer8_minwidth=7 midlayer8_maxwidth=7 midlayer8_prefwidth=7 bottomlayer_maxgap=6.5 bottomlayer_prefgap=6.5 bottomlayer_minwidth=4.5 bottomlayer_maxwidth=6.2 bottomlayer_prefwidth=4.5 maxuncoupledlength=1000
FabricationTestPointUsage TestPointUsage [All] p1: valid=2 allowmultiple=FALSE
FabricationTestpoint Testpoint [All] p1: side=3 testpointundercomponent=TRUE minsize=40 maxsize=100 preferedsize=60 minholesize=0 maxholesize=40 preferedholesize=32 testpointgrid=1 allowsidetop=TRUE allowsidebottom=TRUE usegrid=TRUE gridtolerance=0.01
FanoutControl Fanout_LCC [IsLCC] p1: bgadir=Out bgaviamode=Centered fanoutstyle=Auto fanoutdirection=Alternating viagrid=1 // Fanout_LCC (Default Rule)
FanoutControl Fanout_BGA [IsBGA] p2: bgadir=Out bgaviamode=Centered fanoutstyle=Auto fanoutdirection=Alternating viagrid=1 // Fanout_BGA (Default Rule)
FanoutControl Fanout_Default [All] p4: bgadir=Out bgaviamode=Centered fanoutstyle=Auto fanoutdirection=Alternating viagrid=1 // Fanout_Default (Default Rule)
FanoutControl Fanout_Small [(CompPinCount < 5)] p5: bgadir=Out bgaviamode=Centered fanoutstyle=Auto fanoutdirection=OutThenIn viagrid=1 // Fanout_Small (Default Rule)
HoleSize [All] p1: absolutevalues=TRUE maxlimit=251 minlimit=7.87 maxpercent=80.000 minpercent=20.000
HoleToHoleClearance HoleToHoleClearance_MH [HasFootprint('MTGP_252mil_157mil_6Via') and IsVia vs HasFootprint('MTGP_252mil_157mil_6Via') and IsThruPin] p1: gap=9 allowstackedmicrovias=TRUE
HoleToHoleClearance [All] p2: gap=10 allowstackedmicrovias=TRUE
MinimumAnnularRing MinimumAnnularRing_ThermalPadVias [IsVia and InAnyComponent] p1: minimumring=5.91
MinimumAnnularRing [All] p2: minimumring=5
MinimumSolderMaskSliver MinimumSolderMaskSliver_Logo [InComponentClass('Logo') vs InComponentClass('Logo')] p1: minsoldermaskwidth=0.7
MinimumSolderMaskSliver [All] p2: minsoldermaskwidth=4
PlaneConnect [All] p1: planeconnectstyle=Relief reliefexpansion=10 reliefentries=4 reliefconductorwidth=10 reliefairgap=10
PolygonConnect PolygonConnect_Via [InAnyComponent and IsVia] p1: thpad.connectstyle=Relief thpad.reliefconductorwidth=10 thpad.reliefentries=4 thpad.polygonreliefangle="90 Angle" thpad.airgapwidth=10 smdpad.connectstyle=Relief smdpad.reliefconductorwidth=10 smdpad.reliefentries=4 smdpad.polygonreliefangle="90 Angle" smdpad.airgapwidth=10 via.connectstyle=Direct via.reliefconductorwidth=10 via.reliefentries=4 via.polygonreliefangle="90 Angle" via.airgapwidth=10
PolygonConnect PolygonConnect_MH [HasFootprint('MTGP_252mil_157mil_6Via') and IsThruPin] p2: connectstyle=Direct reliefconductorwidth=10 reliefentries=4 polygonreliefangle="90 Angle" airgapwidth=10
PolygonConnect [All] p3: thpad.connectstyle=Relief thpad.reliefconductorwidth=10 thpad.reliefentries=4 thpad.polygonreliefangle="90 Angle" thpad.airgapwidth=10 smdpad.connectstyle=Relief smdpad.reliefconductorwidth=10 smdpad.reliefentries=4 smdpad.polygonreliefangle="90 Angle" smdpad.airgapwidth=10 via.connectstyle=Relief via.reliefconductorwidth=10 via.reliefentries=4 via.polygonreliefangle="90 Angle" via.airgapwidth=8
RoomDefinition Room_U2 [InComponentClass('Components Class 1')] p1: confinementstyle=ConfineIn formatcopy=TRUE lockcomponents=FALSE outline 2848.67,1217.29 3757.17,1217.29 3757.17,331.39 2848.67,331.39
RoutingVias ThermalPadVias [IsVia and InAnyComponent] p1: holewidth=7.87 width=19.68 viastyle="Through Hole" minholewidth=7.87 minwidth=19.68 maxholewidth=20 maxwidth=40
RoutingVias [All] p2: holewidth=16 width=34 viastyle="Through Hole" minholewidth=8 minwidth=18 maxholewidth=40 maxwidth=65
SilkToBoardRegionClearance [Not ((IsComment or IsDesignator) And (Hide <> 'False')) and not InRegion(1000,500,4000,800)] p1:
SilkToSilkClearance SilkToSilkClearance_Pb-FreeLogo [(HasFootprint('Pb-Free_Overlay_Medium') OR HasFootprint('Pb-Free_Overlay_Small')) vs (HasFootprint('Pb-Free_Overlay_Medium') OR HasFootprint('Pb-Free_Overlay_Small'))] p1: silktosilkclearance=0
SilkToSilkClearance [All] p2: silktosilkclearance=4
SilkToSolderMaskClearance SilkToComponentPadClearance [(IsPad or IsFill or IsRegion) and InAnycomponent] p1: minsilkscreentomaskgap=4 clearancetoexposedcopper=TRUE
SilkToSolderMaskClearance "Silk to Solder Mask Opening" [All] p2: minsilkscreentomaskgap=4 clearancetoexposedcopper=FALSE
SolderMaskExpansion SolderMaskExpansion_PTH [IsThruPin] p1: expansion=2.5
SolderMaskExpansion [All] p2: expansion=0
UnRoutedNet [All] p1: checkbadconnections=TRUE
Width [All] p1: maxlimit=100 minlimit=5.5 preferedwidth=10 toplayer_minwidth=6.2 bottomlayer_minwidth=6.2 minimp=50.000000 maximp=50.000000 favimp=50.000000 checkconnectedcopper=TRUE
14 further rules are at their usual default settings.

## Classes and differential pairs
component class TIDA-08007_VideoInterface: J6 U7 U9 U10 U11
component class TIDA-08007_TPS99000Interface: C17 C18 C19 C20 C22 C23 C24 C25 C26 C27 C31 C34 C505 C519 C521 C526 C550 C557 C560 C561 C575 C576 C578 C579 C580 C581 C582 C583 C584 C585 C586 C587 D3 D500 FB502 FB503 FB504 J4 J5 L4 L5 R4 R5 R6 R7 R8 R9 R10 R20 R21 R504 R505 R507 R509 R514 R515 R517 R518 R519 R520 R521 R522 R523 R524 R525 R526 R527 R528 R529 R530 R531 R541 R542 R543 R544 R545 R546 R547 TP4 TP6 TP7 U4
component class TIDA-08007_Power: C1 C2 C3 C4 C5 C6 C7 C8 C9 C10 C11 C12 C13 C14 C15 C16 C21 C53 C54 C55 D1 D2 D4 J1 L1 L2 L3 L6 L7 L8 Q1 R1 R2 R3 TP1 TP2 TP3 TP5 TP8 TP9 U1 U2 U3 U12
component class TIDA-08007_DMDPower: C28 C29 C30 C32 C33 C35 C36 C37 C40 C41 C43 C47 C567 C570 C571 C577 J500
component class TIDA-08007_DMDInterface: C51 C52 R11 R14 R16 R22 R23 R25 R26 U8
component class TIDA-08007_DLPC230Power: C42 C46 C48 C49 C50 C501 C502 C503 C504 C506 C507 C508 C509 C510 C511 C512 C513 C514 C515 C516 C517 C518 C520 C522 C523 C524 C525 C527 C528 C529 C530 C531 C532 C533 C534 C535 C536 C537 C538 C539 C540 C541 C542 C543 C544 C545 C546 C547 C548 C549 C551 C552 C553 C554 C555 C556 C558 C559 C562 C563 C564 C565 FB1 FB500 FB501 FB505 FB506 FB507 FB508 FB509 FB510 R12 R13 R18 R19 R503 Y1
component class TIDA-08007_DLPC230Interface: C38 C39 C44 C45 C500 C568 C569 C572 C573 C574 J2 J3 R15 R17 R500 R501 R502 R510 R511 R512 R513 R516 R534 R535 R536 R537 R538 R539 R540 U5 U500 U501 U502
component class TIDA-08007_DLPC230GPIO: C566 R24 R506 R508 R532 R533 TP10 U6
component class Logo: Logo3
component class TIDA-08007_Hardware: FID1 FID2 FID3 FID500 FID501 FID502 Logo1 Logo2 Logo3 Logo4 MH1 MH2 ZZ1 ZZ2 ZZ3
component class FiducialMark: FID1 FID2 FID3 FID500 FID501 FID502
component class AssemblyNote: ZZ1 ZZ2 ZZ3
differential pair TMP411: +TMP411_P -TMP411_N
differential pair TEMP: +TEMP_P -TEMP_N
differential pair DMD_LS0_WDATA: +DMD_LS0_WDATA_P -DMD_LS0_WDATA_N
differential pair DMD_LS0_CLK: +DMD_LS0_CLK_P -DMD_LS0_CLK_N
differential pair DMD_HS1_WDATA7: +DMD_HS1_WDATA7_P -DMD_HS1_WDATA7_N
differential pair DMD_HS1_WDATA6: +DMD_HS1_WDATA6_P -DMD_HS1_WDATA6_N
differential pair DMD_HS1_WDATA5: +DMD_HS1_WDATA5_P -DMD_HS1_WDATA5_N
differential pair DMD_HS1_WDATA4: +DMD_HS1_WDATA4_P -DMD_HS1_WDATA4_N
differential pair DMD_HS1_WDATA3: +DMD_HS1_WDATA3_P -DMD_HS1_WDATA3_N
differential pair DMD_HS1_WDATA2: +DMD_HS1_WDATA2_P -DMD_HS1_WDATA2_N
differential pair DMD_HS1_WDATA1: +DMD_HS1_WDATA1_P -DMD_HS1_WDATA1_N
differential pair DMD_HS1_WDATA0: +DMD_HS1_WDATA0_P -DMD_HS1_WDATA0_N
differential pair DMD_HS1_CLK: +DMD_HS1_CLK_P -DMD_HS1_CLK_N
differential pair DMD_HS0_WDATA7: +DMD_HS0_WDATA7_P -DMD_HS0_WDATA7_N
differential pair DMD_HS0_WDATA6: +DMD_HS0_WDATA6_P -DMD_HS0_WDATA6_N
differential pair DMD_HS0_WDATA5: +DMD_HS0_WDATA5_P -DMD_HS0_WDATA5_N
differential pair DMD_HS0_WDATA4: +DMD_HS0_WDATA4_P -DMD_HS0_WDATA4_N
differential pair DMD_HS0_WDATA3: +DMD_HS0_WDATA3_P -DMD_HS0_WDATA3_N
differential pair DMD_HS0_WDATA2: +DMD_HS0_WDATA2_P -DMD_HS0_WDATA2_N
differential pair DMD_HS0_WDATA1: +DMD_HS0_WDATA1_P -DMD_HS0_WDATA1_N
differential pair DMD_HS0_WDATA0: +DMD_HS0_WDATA0_P -DMD_HS0_WDATA0_N
differential pair DMD_HS0_CLK: +DMD_HS0_CLK_P -DMD_HS0_CLK_N
differential pair L1_CLK: +L1_CLK_P -L1_CLK_N
differential pair L1_DATA0: +L1_DATA0_P -L1_DATA0_N
differential pair L1_DATA1: +L1_DATA1_P -L1_DATA1_N
differential pair L1_DATA2: +L1_DATA2_P -L1_DATA2_N
differential pair L1_DATA3: +L1_DATA3_P -L1_DATA3_N

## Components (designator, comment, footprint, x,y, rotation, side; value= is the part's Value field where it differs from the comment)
C1 "EMZR500ARA221MHA0G" CAPSMT_62_HA0 253.06,1066.52 r180 top locked value=220uF (schematic designator C97)
C2 "EMZR500ARA221MHA0G" CAPSMT_62_HA0 253.06,682.66 r180 top locked value=220uF (schematic designator C98)
C3 "EMVA500ADA220MF55G" CAPSMT_62_F55 201.88,289.76 r180 top locked value=22uF (schematic designator C99)
C4 "CL32B106KBJNNWE" 1210_270 560.04,1407.48 r0 top locked value=10uF (schematic designator C92)
C5 "EMK107BB7225MA-T" 0603 650.85,953.65 r0 top locked value=2.2uF (schematic designator C93)
C6 "C4532X7R1H685M250KB" 1812_280 699.42,636.79 r90 top locked value=6.8uF (schematic designator C100)
C7 "C2012X6S1C156M125AC" 0805_HV 708.88,142.14 r90 top locked value=15uF (schematic designator C108)
C8 "GCM31CC71H475KA03L" 1206_180 710.7,386.44 r90 top locked value=4.7uF (schematic designator C102)
C9 "C0603C223K5RACTU" 0603 790.7,386.44 r270 top locked value=0.022uF (schematic designator C104)
C10 "LMK212B7105KG-T" 0805_HV 890.54,562.93 r180 top locked value=1uF (schematic designator C111)
C11 "08055C153KAT2A" 0805_HV 969.19,1570.36 r270 top locked value=0.015uF (schematic designator C101)
C12 "GCM155R71C104JA55D" 0402 964,463.01 r270 top locked value=0.1uF (schematic designator C105)
C13 "C0603C223K5RACTU" 0603 970.7,352.77 r270 top locked value=0.022uF (schematic designator C103)
C14 "C2012X6S1C156M125AC" 0805_HV 1052.9,142.14 r90 top locked value=15uF (schematic designator C109)
C15 "C2012X7R1A106M125AC" 0805_HV 1135,1790 r180 top locked value=10uF (schematic designator C96)
C16 "C2012X7R1A106M125AC" 0805_HV 1135.84,1504.88 r90 top locked value=10uF (schematic designator C94)
C17 "GRM155R71H331KA01D" 0402 1147.64,797.24 r180 top locked value=330pF (schematic designator C142)
C18 "EMK107BB7225MA-T" 0603 1176.36,336.63 r180 top locked value=2.2uF (schematic designator C119)
C19 "EMK107BB7225MA-T" 0603 1176.36,413.39 r180 top locked value=2.2uF (schematic designator C118)
C20 "EMK107BB7225MA-T" 0603 1172.64,513.23 r270 top locked value=2.2uF (schematic designator C112)
C21 "C2012X7R1A106M125AC" 0805_HV 1230.17,1504.88 r90 top locked value=10uF (schematic designator C95)
C22 "GCM155R71C104JA55D" 0402 1229.68,525.21 r270 top locked value=0.1uF (schematic designator C113)
C23 "GRM188R71E474KA12D" 0603 1323.46,874.92 r180 top locked value=0.47uF (schematic designator C139)
C24 "EMK107BB7225MA-T" 0603 1382.51,89.16 r180 top locked value=2.2uF (schematic designator C125)
C25 "GCM188R71E105KA64D" 0603 1452.13,944.48 r0 top locked value=1uF (schematic designator C138)
C26 "GCM188R71H224KA64D" 0603 1452.13,874.85 r0 top locked value=0.22uF (schematic designator C137)
C27 "EMK107BB7225MA-T" 0603 1511.19,89.16 r0 top locked value=2.2uF (schematic designator C126)
C28 "GCM155R71C104JA55D" 0402 1539.37,1408.39 r180 top locked value=0.1uF (schematic designator C81)
C29 "GCM155R71C104JA55D" 0402 1564.37,1793.59 r180 top locked value=0.1uF (schematic designator C78)
C30 "GCM155R71C104JA55D" 0402 1569.8,1008.39 r270 top locked value=0.1uF (schematic designator C80)
C31 "GCM155R71C104JA55D" 0402 1712.6,99.29 r180 top locked value=0.1uF (schematic designator C124)
C32 "GCM188R71H224KA64D" 0603 1768.12,1013.39 r180 top locked value=0.22uF (schematic designator C90)
C33 "GCM188R71H224KA64D" 0603 1850.33,925.44 r0 top locked value=0.22uF (schematic designator C88)
C34 "GCM155R71C104JA55D" 0402 1988.91,489.15 r270 top locked value=0.1uF (schematic designator C133)
C35 "GCM155R71C104JA55D" 0402 2019.85,984.76 r270 top locked value=0.1uF (schematic designator C76)
C36 "GCM155R71C104JA55D" 0402 2145.9,984.76 r270 top locked value=0.1uF (schematic designator C77)
C37 "GCM155R71C104JA55D" 0402 2452.76,979.52 r180 top locked value=0.1uF (schematic designator C83)
C38 "CGA2B2NP01H220J050BA" 0402 2488.48,361.77 r90 top locked value=22pF (schematic designator C3)
C39 "GRM155R71C222KA01D" 0402 2538.48,361.77 r90 top locked value=2200pF (schematic designator C4)
C40 "GCM155R71C104JA55D" 0402 2568.39,1158.39 r180 top locked value=0.1uF (schematic designator C84)
C41 "GCM155R71C104JA55D" 0402 2545.94,1432.01 r90 top locked value=0.1uF (schematic designator C79)
C42 "GCM1885C1H150JA16D" 0603 2604.54,923.21 r180 top locked value=15pF (schematic designator C66)
C43 "GCM155R71C104JA55D" 0402 2577.76,1767.76 r90 top locked value=0.1uF (schematic designator C82)
C44 "GRM155R71C222KA01D" 0402 2588.48,361.77 r90 top locked value=2200pF (schematic designator C5)
C45 "GRM155R71C222KA01D" 0402 2688.48,361.77 r90 top locked value=2200pF (schematic designator C6)
C46 "GCM1885C1H150JA16D" 0603 2706.1,738.66 r270 top locked value=15pF (schematic designator C65)
C47 "GCM155R71C104JA55D" 0402 2709.57,1033.39 r270 top locked value=0.1uF (schematic designator C85)
C48 "GCM155R71C104JA55D" 0402 2914.84,1309.47 r90 top locked value=0.1uF (schematic designator C30)
C49 "GCM155R71C104JA55D" 0402 2964.21,1309.47 r90 top locked value=0.1uF (schematic designator C36)
C50 "C2012X7R1A106M125AC" 0805_HV 3038.27,1335.47 r90 top locked value=10uF (schematic designator C26)
C51 "CGA2B2C0G1H101J050BA" 0402 3087.46,1560.39 r270 top locked value=100pF (schematic designator C75)
C52 "GCM155R71C104JA55D" 0402 3218.32,1651.82 r0 top locked value=0.1uF (schematic designator C74)
C53 "C2012X7R1A106M125AC" 0805_HV 3914.55,1302.84 r90 top locked value=10uF (schematic designator C106)
C54 "CGA5L1X7R0J226M160AC" 1206_180 3974.55,1512.84 r90 top locked value=22uF (schematic designator C110)
C55 "CGA5L1X7R0J226M160AC" 1206_180 3974.55,1065.99 r270 top locked value=22uF (schematic designator C107)
C500 "GCM155R71C104JA55D" 0402 4075.41,1903.81 r0 bottom locked value=0.1uF (schematic designator C7)
C501 "EMK107BB7225MA-T" 0603 3701.57,1032.5 r0 bottom locked value=2.2uF (schematic designator C46)
C502 "GCM155R71C104JA55D" 0402 3689.75,1090.05 r0 bottom locked value=0.1uF (schematic designator C48)
C503 "GCM155R71C104JA55D" 0402 3685.38,540.36 r0 bottom locked value=0.1uF (schematic designator C63)
C504 "GCM155R71C104JA55D" 0402 3685.38,490.99 r0 bottom locked value=0.1uF (schematic designator C64)
C505 "CGA2B2NP01H220J050BA" 0402 3687.54,205.71 r270 bottom locked value=22pF (schematic designator C120)
C506 "GCM155R71C104JA55D" 0402 3638.8,612.66 r0 bottom locked value=0.1uF (schematic designator C58)
C507 "GCM155R71C104JA55D" 0402 3626.76,715.28 r90 bottom locked value=0.1uF (schematic designator C49)
C508 "GCM155R71C104JA55D" 0402 3588.39,1060.7 r0 bottom locked value=0.1uF (schematic designator C23)
C509 "GCM155R71C104JA55D" 0402 3569.63,491.01 r0 bottom locked value=0.1uF (schematic designator C42)
C510 "GCM155R71C104JA55D" 0402 3587.39,1153.04 r90 bottom locked value=0.1uF (schematic designator C47)
C511 "GCM155R71C104JA55D" 0402 3557.96,562.49 r90 bottom locked value=0.1uF (schematic designator C44)
C512 "GCM155R71C104JA55D" 0402 3520.87,736.03 r180 bottom locked value=0.1uF (schematic designator C24)
C513 "GCM155R71C104JA55D" 0402 3520.87,686.25 r180 bottom locked value=0.1uF (schematic designator C40)
C514 "GCM155R71C104JA55D" 0402 3520.87,637.29 r180 bottom locked value=0.1uF (schematic designator C52)
C515 "GCM155R71C104JA55D" 0402 3520.87,1011.62 r180 bottom locked value=0.1uF (schematic designator C22)
C516 "GCM155R71C104JA55D" 0402 3520.87,961.84 r180 bottom locked value=0.1uF (schematic designator C57)
C517 "GCM155R71C104JA55D" 0402 3520.87,912.88 r180 bottom locked value=0.1uF (schematic designator C50)
C518 "GCM155R71C104JA55D" 0402 3548.37,826.89 r90 bottom locked value=0.1uF (schematic designator C25)
C519 "CGA2B2NP01H220J050BA" 0402 3523.62,338.08 r90 bottom locked value=22pF (schematic designator C121)
C520 "GCM155R71C104JA55D" 0402 3487.65,1090.05 r180 bottom locked value=0.1uF (schematic designator C43)
C521 "CGA2B2NP01H220J050BA" 0402 3476.7,247.05 r0 bottom locked value=22pF (schematic designator C122)
C522 "EMK107BB7225MA-T" 0603 3490.92,823.8 r90 bottom locked value=2.2uF (schematic designator C21)
C523 "GCM155R71C104JA55D" 0402 3488.97,562.86 r90 bottom locked value=0.1uF (schematic designator C41)
C524 "GCM155R71C104JA55D" 0402 3425.07,984.12 r270 bottom locked value=0.1uF (schematic designator C51)
C525 "GCM155R71C104JA55D" 0402 3408.99,566.02 r90 bottom locked value=0.1uF (schematic designator C62)
C526 "CGA2B2NP01H220J050BA" 0402 3373.7,247.05 r0 bottom locked value=22pF (schematic designator C123)
C527 "GCM155R71C104JA55D" 0402 3375.86,984.12 r270 bottom locked value=0.1uF (schematic designator C14)
C528 "GCM155R71C104JA55D" 0402 3360.14,566.02 r90 bottom locked value=0.1uF (schematic designator C61)
C529 "GCM155R71C104JA55D" 0402 3332.17,1090.05 r180 bottom locked value=0.1uF (schematic designator C53)
C530 "GCM155R71C104JA55D" 0402 3326.64,984.12 r270 bottom locked value=0.1uF (schematic designator C13)
C531 "GCM155R71C104JA55D" 0402 3311.29,566.02 r90 bottom locked value=0.1uF (schematic designator C39)
C532 "GCM155R71C104JA55D" 0402 3277.43,984.12 r270 bottom locked value=0.1uF (schematic designator C12)
C533 "GCM155R71C104JA55D" 0402 3262.44,566.02 r90 bottom locked value=0.1uF (schematic designator C59)
C534 "GCM155R71C104JA55D" 0402 3233.06,1147.81 r90 bottom locked value=0.1uF (schematic designator C54)
C535 "EMK107BB7225MA-T" 0603 3185.56,958.54 r0 bottom locked value=2.2uF (schematic designator C16)
C536 "GCM155R71C104JA55D" 0402 3213.38,565.81 r90 bottom locked value=0.1uF (schematic designator C15)
C537 "GCM155R71C104JA55D" 0402 3177.94,1059.24 r0 bottom locked value=0.1uF (schematic designator C60)
C538 "GCM155R71C104JA55D" 0402 3173.57,1015.68 r0 bottom locked value=0.1uF (schematic designator C20)
C539 "GCM155R71C104JA55D" 0402 3157.07,1129.42 r180 bottom locked value=0.1uF (schematic designator C55)
C540 "GCM155R71C104JA55D" 0402 3164.73,566.02 r90 bottom locked value=0.1uF (schematic designator C38)
C541 "GCM155R71C104JA55D" 0402 3162.88,712.09 r270 bottom locked value=0.1uF (schematic designator C56)
C542 "C2012X7R1A106M125AC" 0805_HV 3143.19,1232.47 r90 bottom locked value=10uF (schematic designator C37)
C543 "GCM155R71C104JA55D" 0402 3115.88,566.02 r90 bottom locked value=0.1uF (schematic designator C18)
C544 "GCM155R71C104JA55D" 0402 3092.31,984.12 r270 bottom locked value=0.1uF (schematic designator C17)
C545 "GCM155R71C104JA55D" 0402 3058.15,1090.05 r0 bottom locked value=0.1uF (schematic designator C28)
C546 "GCM155R71C104JA55D" 0402 3075.58,1194.64 r90 bottom locked value=0.1uF (schematic designator C27)
C547 "GCM155R71C104JA55D" 0402 3071.12,727.58 r90 bottom locked value=0.1uF (schematic designator C45)
C548 "GCM155R71C104JA55D" 0402 3067.02,566.02 r90 bottom locked value=0.1uF (schematic designator C19)
C549 "GCM155R71C104JA55D" 0402 3043.1,984.12 r90 bottom locked value=0.1uF (schematic designator C67)
C550 "CGA2B2NP01H220J050BA" 0402 3007.87,311.2 r0 bottom locked value=22pF (schematic designator C130)
C551 "GCM155R71C104JA55D" 0402 3029.29,1194.64 r90 bottom locked value=0.1uF (schematic designator C35)
C552 "GCM155R71C104JA55D" 0402 2981.09,823.01 r180 bottom locked value=0.1uF (schematic designator C70)
C553 "GCM155R71C104JA55D" 0402 2981.09,470.68 r180 bottom locked value=0.1uF (schematic designator C31)
C554 "GCM155R71C104JA55D" 0402 2977.88,584.86 r180 bottom locked value=0.1uF (schematic designator C29)
C555 "GCM155R71C104JA55D" 0402 2976.47,744.27 r180 bottom locked value=0.1uF (schematic designator C73)
C556 "GCM155R71C104JA55D" 0402 2998.59,398.38 r90 bottom locked value=0.1uF (schematic designator C33)
C557 "CGA2B2NP01H220J050BA" 0402 2913.39,221.42 r270 bottom locked value=22pF (schematic designator C128)
C558 "GCM155R71C104JA55D" 0402 2986.34,1109.09 r270 bottom locked value=0.1uF (schematic designator C34)
C559 "GCM155R71C104JA55D" 0402 2899.1,391.38 r180 bottom locked value=0.1uF (schematic designator C32)
C560 "CGA2B2NP01H220J050BA" 0402 2795.35,244.33 r180 bottom locked value=22pF (schematic designator C127)
C561 "CGA2B2NP01H220J050BA" 0402 2992.24,236.3 r0 bottom locked value=22pF (schematic designator C129)
C562 "GCM219R71C105KA37D" 0805_HV 2794.05,643.98 r90 bottom locked value=1uF (schematic designator C72)
C563 "GCM219R71C105KA37D" 0805_HV 2774.43,801.98 r90 bottom locked value=1uF (schematic designator C69)
C564 "GCM155R71C104JA55D" 0402 2597.02,638.98 r90 bottom locked value=0.1uF (schematic designator C71)
C565 "GCM155R71C104JA55D" 0402 2567.4,801.98 r90 bottom locked value=0.1uF (schematic designator C68)
C566 "GCM155R71C104JA55D" 0402 2513.16,545.63 r270 bottom locked value=0.1uF (schematic designator C1)
C567 "GCM188R71H224KA64D" 0603 2459.25,1850.8 r0 bottom locked value=0.22uF (schematic designator C86)
C568 "CGA2B2NP01H220J050BA" 0402 2428.09,250.67 r180 bottom locked value=22pF (schematic designator C2)
C569 "CGA2B2NP01H220J050BA" 0402 2355.79,344.27 r0 bottom locked value=22pF (schematic designator C8)
C570 "GCM188R71H224KA64D" 0603 2366.91,844.49 r270 bottom locked value=0.22uF (schematic designator C89)
C571 "GCM188R71H224KA64D" 0603 2302.76,844.49 r270 bottom locked value=0.22uF (schematic designator C91)
C572 "CGA2B2NP01H220J050BA" 0402 2251.73,334.27 r180 bottom locked value=22pF (schematic designator C9)
C573 "CGA2B2NP01H220J050BA" 0402 2175.18,371.77 r90 bottom locked value=22pF (schematic designator C10)
C574 "CGA2B2NP01H220J050BA" 0402 2082.68,320.27 r180 bottom locked value=22pF (schematic designator C11)
C575 "C2012X7R1A106M125AC" 0805_HV 1977.07,800.53 r90 bottom locked value=10uF (schematic designator C134)
C576 "GCM155R71C104JA55D" 0402 1906.98,761.07 r90 bottom locked value=0.1uF (schematic designator C131)
C577 "GCM188R71H224KA64D" 0603 1757.41,1849.63 r0 bottom locked value=0.22uF (schematic designator C87)
C578 "GCM155R71C104JA55D" 0402 1653.54,780.91 r270 bottom locked value=0.1uF (schematic designator C132)
C579 "EMK107BB7225MA-T" 0603 1593.2,773.04 r270 bottom locked value=2.2uF (schematic designator C114)
C580 "GCM155R71C104JA55D" 0402 1535.43,780.91 r270 bottom locked value=0.1uF (schematic designator C115)
C581 "EMK107BB7225MA-T" 0603 1331.52,459.62 r0 bottom locked value=2.2uF (schematic designator C116)
C582 "EMK107BB7225MA-T" 0603 1312.24,554.25 r270 bottom locked value=2.2uF (schematic designator C136)
C583 "EMK107BB7225MA-T" 0603 1279.03,390.52 r0 bottom locked value=2.2uF (schematic designator C117)
C584 "GCM155R71C104JA55D" 0402 1312.24,672.37 r90 bottom locked value=0.1uF (schematic designator C135)
C585 "GCM188R71H224KA64D" 0603 1220.37,765.47 r90 bottom locked value=0.22uF (schematic designator C140)
C586 "CGA2B2X7R1H681K050BA" 0402 1227.06,563.33 r270 bottom locked value=680pF (schematic designator C143)
C587 "GCM188R71E105KA64D" 0603 1154.41,765.47 r90 bottom locked value=1uF (schematic designator C141)
D1 "SMBJ24A-13-F" SMB 590.55,1766.81 r180 top locked value=24V
D2 "SMBJ16A-13-F" SMB 590.55,1574.8 r180 top locked value=16V
D3 "MBR0540T1G" SOD-123 1027.73,677.64 r90 top locked value=40V (schematic designator D4)
D4 "MBR1020VL" SOD-123F 1325,1499.88 r90 top locked value=20V (schematic designator D3)
D500 "MMSZ5234B-7-F" SOD-123 1027.75,513.23 r270 bottom locked value=6.2V (schematic designator D5)
FB1 "FBMH1608HM101-TV" FP-FBMH1608HM101-TV_0603-MFG 3108.54,1322.02 r270 top locked (schematic designator FB3)
FB500 "FBMH1608HM101-TV" FP-FBMH1608HM101-TV_0603-MFG 3709.44,973.94 r180 bottom locked (schematic designator FB4)
FB501 "FBMH1608HM101-TV" FP-FBMH1608HM101-TV_0603-MFG 3435.02,831.68 r270 bottom locked (schematic designator FB2)
FB502 "FBMH1608HM101-TV" FP-FBMH1608HM101-TV_0603-MFG 3188.98,123.92 r270 bottom (schematic designator FB12)
FB503 "FBMH1608HM101-TV" FP-FBMH1608HM101-TV_0603-MFG 3132.48,123.92 r270 bottom (schematic designator FB11)
FB504 "FBMH1608HM101-TV" FP-FBMH1608HM101-TV_0603-MFG 3075.98,123.92 r270 bottom (schematic designator FB10)
FB505 "FBMH1608HM101-TV" FP-FBMH1608HM101-TV_0603-MFG 3209.3,903.55 r180 bottom locked (schematic designator FB1)
FB506 "100OHM, DCR=35mOHM" FP-FBMH1608HM101-TV_0603-MFG 3074.9,864.11 r90 bottom locked (schematic designator FB5)
FB507 "FBMH1608HM101-TV" FP-FBMH1608HM101-TV_0603-MFG 2686.35,683.98 r0 bottom locked (schematic designator FB9)
FB508 "FBMH1608HM101-TV" FP-FBMH1608HM101-TV_0603-MFG 2686.35,603.98 r0 bottom locked (schematic designator FB8)
FB509 "FBMH1608HM101-TV" FP-FBMH1608HM101-TV_0603-MFG 2666.74,841.98 r0 bottom locked (schematic designator FB7)
FB510 "FBMH1608HM101-TV" FP-FBMH1608HM101-TV_0603-MFG 2666.74,761.98 r0 bottom locked (schematic designator FB6)
FID1 "Fiducial" Fiducial10-20 118.11,78.74 r0 top locked (schematic designator FID2)
FID2 "Fiducial" Fiducial10-20 383.86,1978.35 r0 top locked (schematic designator FID1)
FID3 "Fiducial" Fiducial10-20 4108.09,1801.55 r0 top locked
FID500 "Fiducial" Fiducial10-20 4108.09,1801.55 r180 bottom locked (schematic designator FID4)
FID501 "Fiducial" Fiducial10-20 383.86,1978.35 r180 bottom locked (schematic designator FID5)
FID502 "Fiducial" Fiducial10-20 118.11,78.74 r180 bottom locked (schematic designator FID6)
J1 "502352-0200" FP-502352-0200_HDR2-MFG 205.51,1535.43 r270 top locked (schematic designator J4)
J2 "501568-0707" FP-501568-0707_HDR7-MFG 2224.41,118.11 r0 top locked
J3 "203559-0607" FP-203559-0607_HDR6-MFG 2608.27,118.11 r0 top locked (schematic designator J1)
J4 "501568-0907" FP-501568-0907_HDR9-MFG 3031.5,118.11 r0 top locked (schematic designator J6)
J5 "501568-0707" FP-501568-0707_HDR7-MFG 3484.25,118.11 r0 top locked
J6 "505110-1692" FP-505110-1692_CONN_SMT_12MM7_5MM25-MFG 4153.54,620.85 r90 top locked (schematic designator J7)
J500 "450-2.700-L-13.25-149" FP-450-2.700-L-13.25-149_SOCKET_CPGA149-MFG 2082.87,1358.39 r180 bottom locked (schematic designator J3)
L1 "744773039" WE-PD2-S 499.28,350.77 r270 top locked value=3.9uH (schematic designator L2)
L2 "742792114" 1206 548.34,615.57 r270 top locked value="50 ohm" (schematic designator L3)
L3 "SDE0604A-2R7M" SDE0604A 880.7,162.14 r270 top locked value=2.7uH (schematic designator L5)
L4 "FDSD0420D-100M" FDSD0420 1171.26,676.16 r270 top locked value=10uH (schematic designator L8)
L5 "120 Ohm @ 100MHz" 0402 1110.31,521.1 r90 top locked value="120 ohm" (schematic designator L7)
L6 "VLCF5020T-100M1R1-1" VLCF5020 1325,1730.83 r270 top locked value=10uH (schematic designator L1)
L7 "78438335047" WE-MAIA_3015 4099.88,1449.85 r0 top locked value=4.7uH (schematic designator L6)
L8 "78438335047" WE-MAIA_3015 4099.88,1134.73 r0 top locked value=4.7uH (schematic designator L4)
Logo1 "CE Mark" CE_Mark_5mm 3638.45,1363.91 r0 top locked
Logo2 "FCC disclaimer" FCC_disclaimer 2106.3,1958.66 r0 top locked (schematic designator Logo3)
Logo3 "Texas Instruments" TI_Stacked_Overlay_Small 3620.78,1907.26 r0 top locked (schematic designator Logo2)
Logo4 "WEEE logo" WEEE_Minimum 3695.39,1676.28 r0 top locked
MH1 "MTG_Pads" MTGP_252mil_157mil_6Via 173.23,1874.02 r0 top locked (schematic designator MH2)
MH2 "MTG_Pads" MTGP_252mil_157mil_6Via 4039.37,173.23 r0 top locked (schematic designator MH1)
Q1 "CSD17313Q2Q1" DQK0006C 566.11,1231.32 r90 top locked value=30V
R1 "CRCW04026K98FKED" 0402 992.81,1676.5 r0 top locked value=6.98k (schematic designator R36)
R2 "CRCW040245K3FKED" 0402 992.81,1726.09 r180 top locked value=45.3k (schematic designator R34)
R3 "CRCW080510K5FKEA" 0805_HV 1000.81,1830 r270 top locked value=10.5k (schematic designator R35)
R4 "ERJ-2RKF1003X" 0402 1324.8,937.78 r0 top locked value=100k (schematic designator R51)
R5 "ERJ-2RKF5102X" 0402 1452.13,1005.07 r180 top locked value=51.0k (schematic designator R50)
R6 "ERJ-2RKF33R0X" 0402 1713.02,895.65 r270 top locked value=33.0 (schematic designator R52)
R7 "ERJ-2GEJ103X" 0402 1762.08,895.65 r270 top locked value=10k (schematic designator R68)
R8 "ERJ-2GEJ103X" 0402 1864.65,868.15 r180 top locked value=10k (schematic designator R67)
R9 "ERJ-2RKF33R0X" 0402 2080.03,566.65 r180 top locked value=33.0 (schematic designator R55)
R10 "ERJ-2RKF2201X" 0402 2052.53,489.15 r90 top locked value=2.20k (schematic designator R54)
R11 "ERJ-2RKF2201X" 0402 2252.76,889.05 r90 top locked value=2.20k (schematic designator R33)
R12 "ERJ-6ENF4222V" 0805_HV 2452.83,641.47 r0 top locked value=42.2k (schematic designator R23)
R13 "ERJ-6ENF4222V" 0805_HV 2452.83,721.47 r0 top locked value=42.2k (schematic designator R22)
R14 "ERJ-2RKF33R0X" 0402 2402.76,887.95 r270 top locked value=33.0 (schematic designator R32)
R15 "ERJ-2GEJ102X" 0402 2439.51,361.77 r90 top locked value=1.0k (schematic designator R7)
R16 "ERJ-2RKF33R0X" 0402 2452.76,887.95 r270 top locked value=33.0 (schematic designator R31)
R17 "ERJ-2RKF2201X" 0402 2638.48,361.77 r90 top locked value=2.20k (schematic designator R5)
R18 "ERJ-6ENF3001V" 0805_HV 2740.53,935.94 r0 top locked value=3.00k (schematic designator R26)
R19 "ERJ-6GEYJ105V" 0805_HV 2774.86,810.15 r270 top locked value=1.0Meg (schematic designator R25)
R20 "ERJ-2GEJ103X" 0402 2790.35,294.33 r0 top locked value=10k (schematic designator R65)
R21 "ERJ-2GEJ103X" 0402 2790.35,359.33 r0 top locked value=10k (schematic designator R64)
R22 "ERJ-6GEYJ560V" 0805_HV 2966.48,1604.68 r180 top locked value=56 (schematic designator R29)
R23 "ERJ-6GEYJ560V" 0805_HV 2966.48,1516.1 r180 top locked value=56 (schematic designator R30)
R24 "ERJ-2GEJ102X" 0402 3160.88,1310.84 r270 top locked value=1.0k (schematic designator R4)
R25 "ERJ-2GEJ102X" 0402 3404.71,1614.28 r0 top locked value=1.0k (schematic designator R27)
R26 "ERJ-2GEJ102X" 0402 3404.71,1560.39 r0 top locked value=1.0k (schematic designator R28)
R500 "ERJ-2RKF3301X" 0402 4075.41,1953.81 r0 bottom locked value=3.30k (schematic designator R11)
R501 "ERJ-2GEJ103X" 0402 4075.41,1653.81 r0 bottom locked value=10k (schematic designator R12)
R502 "ERJ-2GEJ103X" 0402 4075.41,1603.81 r0 bottom locked value=10k (schematic designator R9)
R503 "ERJ-6ENF4222V" 0805_HV 3932.95,905.32 r180 bottom locked value=42.2k (schematic designator R24)
R504 "ERJ-2GEJ103X" 0402 3829.66,172.95 r90 bottom locked value=10k (schematic designator R37)
R505 "ERJ-2GEJ103X" 0402 3768.01,330.08 r180 bottom locked value=10k (schematic designator R41)
R506 "ERJ-2RKF2201X" 0402 3790.72,554.61 r270 bottom locked value=2.20k (schematic designator R2)
R507 "ERJ-6GEYJ750V" 0805_HV 3759.34,189.33 r270 bottom locked value=75 (schematic designator R40)
R508 "ERJ-2RKF2201X" 0402 3741.58,634.99 r90 bottom locked value=2.20k (schematic designator R3)
R509 "ERJ-6GEYJ750V" 0805_HV 3627.84,330.08 r0 bottom locked value=75 (schematic designator R39)
R510 "ERJ-2GEJ103X" 0402 3506.52,1903.81 r180 bottom locked value=10k (schematic designator R8)
R511 "ERJ-2RKF3301X" 0402 3506.52,1603.81 r180 bottom locked value=3.30k (schematic designator R10)
R512 "ERJ-2RKF33R0X" 0402 3515.01,1187.79 r270 bottom locked value=33.0 (schematic designator R13)
R513 "ERJ-2GEJ103X" 0402 3486.92,1267.25 r180 bottom locked value=10k (schematic designator R17)
R514 "ERJ-2RKF33R0X" 0402 3407.84,381.38 r180 bottom locked value=33.0 (schematic designator R73)
R515 "ERJ-2RKF33R0X" 0402 3448.85,473.68 r0 bottom locked value=33.0 (schematic designator R57)
R516 "ERJ-2RKF33R0X" 0402 3463.3,1187.79 r270 bottom locked value=33.0 (schematic designator R15)
R517 "ERJ-2RKF33R0X" 0402 3320.02,397.13 r270 bottom locked value=33.0 (schematic designator R56)
R518 "ERJ-6GEYJ750V" 0805_HV 3294.01,147.36 r270 bottom locked value=75 (schematic designator R38)
R519 "ERJ-2RKF33R0X" 0402 3222.65,311.2 r0 bottom locked value=33.0 (schematic designator R49)
R520 "ERJ-2RKF33R0X" 0402 3262.83,439.5 r270 bottom locked value=33.0 (schematic designator R53)
R521 "ERJ-2GEJ103X" 0402 3403.09,107.36 r180 bottom locked value=10k (schematic designator R42)
R522 "ERJ-2RKF33R0X" 0402 3174.26,478.65 r180 bottom locked value=33.0 (schematic designator R45)
R523 "ERJ-2RKF33R0X" 0402 3146.76,309.15 r270 bottom locked value=33.0 (schematic designator R46)
R524 "ERJ-2GEJ103X" 0402 3088.62,654.08 r0 bottom locked value=10k (schematic designator R43)
R525 "ERJ-2RKF33R0X" 0402 3083.58,323.02 r270 bottom locked value=33.0 (schematic designator R47)
R526 "ERJ-2RKF33R0X" 0402 3146.76,407.57 r270 bottom locked value=33.0 (schematic designator R48)
R527 "ERJ-2GEJ103X" 0402 2813.98,170.71 r90 bottom locked value=10k (schematic designator R66)
R528 "ERJ-2GEJ103X" 0402 2789.45,373.03 r270 bottom locked value=10k (schematic designator R63)
R529 "ERJ-2GEJ102X" 0402 2696.43,547.42 r0 bottom locked value=1.0k (schematic designator R61)
R530 "ERJ-2GEJ103X" 0402 2696.43,500.19 r0 bottom locked value=10k (schematic designator R62)
R531 "ERJ-2GEJ103X" 0402 2696.43,452.95 r180 bottom locked value=10k (schematic designator R44)
R532 "ERJ-2RKF2201X" 0402 2587.97,521.63 r90 bottom locked value=2.20k (schematic designator R1)
R533 "ERJ-2GEJ103X" 0402 2516.77,469.88 r0 bottom locked value=10k (schematic designator R74)
R534 "ERJ-2GEJ102X" 0402 2451.52,168 r270 bottom locked value=1.0k (schematic designator R6)
R535 "ERJ-6GEYJ750V" 0805_HV 2348.26,447.49 r90 bottom locked value=75 (schematic designator R19)
R536 "ERJ-2GEJ103X" 0402 2348.26,578.13 r90 bottom locked value=10k (schematic designator R14)
R537 "ERJ-6GEYJ750V" 0805_HV 2259.26,447.49 r90 bottom locked value=75 (schematic designator R18)
R538 "ERJ-2GEJ103X" 0402 2259.26,578.13 r270 bottom locked value=10k (schematic designator R20)
R539 "ERJ-2GEJ103X" 0402 2178.91,502.68 r270 bottom locked value=10k (schematic designator R21)
R540 "ERJ-6GEYJ750V" 0805_HV 2106.3,425.06 r90 bottom locked value=75 (schematic designator R16)
R541 "ERJ-2GEJ103X" 0402 1893.7,272.98 r0 bottom locked value=10k (schematic designator R70)
R542 "ERJ-2GEJ103X" 0402 1893.7,420.57 r0 bottom locked value=10k (schematic designator R60)
R543 "ERJ-2GEJ103X" 0402 1893.7,371.2 r0 bottom locked value=10k (schematic designator R59)
R544 "ERJ-2GEJ103X" 0402 1893.7,321.83 r0 bottom locked value=10k (schematic designator R69)
R545 "ERJ-3EKF1002V" 0603 1170.02,551.35 r90 bottom locked value=10.0k (schematic designator R72)
R546 "ERJ-3EKF3002V" 0603 1107.69,551.35 r270 bottom locked value=30.0k (schematic designator R71)
R547 "ERJ-2RKF5102X" 0402 1095.5,764.01 r270 bottom locked value=51.0k (schematic designator R58)
TP1 "5015" Testpoint_Keystone_Miniature 383.86,1840.55 r90 top locked (schematic designator TP2)
TP2 "5015" Testpoint_Keystone_Miniature 529.71,103.02 r0 top locked (schematic designator TP6)
TP3 "5015" Testpoint_Keystone_Miniature 815,1768.39 r90 top locked
TP4 "5015" Testpoint_Keystone_Miniature 880.91,697.35 r180 top locked (schematic designator TP10)
TP5 "5015" Testpoint_Keystone_Miniature 1176.34,1338.19 r0 top locked (schematic designator TP4)
TP6 "5015" Testpoint_Keystone_Miniature 1263.98,1143.15 r90 top locked (schematic designator TP9)
TP7 "5015" Testpoint_Keystone_Miniature 1428.51,1143.15 r270 top locked (schematic designator TP8)
TP8 "5015" Testpoint_Keystone_Miniature 3875.47,1101.42 r270 top locked (schematic designator TP5)
TP9 "5015" Testpoint_Keystone_Miniature 3875.47,1469.53 r90 top locked (schematic designator TP7)
TP10 "5015" Testpoint_Keystone_Miniature 3912.44,377.61 r90 top locked (schematic designator TP1)
U1 "LM74610QDGKRQ1" DGK0008A_N 644.38,1064.66 r180 top locked (schematic designator U8)
U2 "LMR36015FSC3RNXTQ1" RNX0012B 880.7,417.93 r180 top locked (schematic designator U10)
U3 "TPS61170QDRVRQ1" DRV0006A 1135,1688.5 r0 top locked (schematic designator U9)
U4 "TPS9900TPZPRQ1" PZP0100K 1614.17,479.31 r180 top locked (schematic designator U12)
U5 "TPD4E05U06QDQARQ1" DQA0010A#1 2224.41,371.65 r90 top locked
U6 "74CBTLV1G125DBVRQ1" DBV0005A_N 2550.56,515.12 r90 top locked (schematic designator U1)
U7 "DLPC230TZDQQ1" ZDQ0324 3311.8,775.09 r90 top locked (schematic designator U2)
U8 "TMP411AQDGKRQ1" DGK0008A_L 3232.23,1560.39 r0 top locked (schematic designator U7)
U9 "TPD4E05U06QDQARQ1" DQA0010A#1 3909.39,768.49 r180 top locked (schematic designator U15)
U10 "TPD4E05U06QDQARQ1" DQA0010A#1 3909.39,650.38 r180 top locked (schematic designator U14)
U11 "TPD4E05U06QDQARQ1" DQA0010A#1 3909.39,532.27 r180 top locked (schematic designator U13)
U12 "TPS62424QDRCRQ1" DRC0010J 4080.94,1295.32 r0 top locked (schematic designator U11)
U500 "MT25QL128ABA8ESF-0AAT" FP-MT25QL128ABA8ESF-0AAT_SOP2-16-MFG 3789.98,1778.81 r180 bottom locked (schematic designator U6)
U501 "TPD4E05U06QDQARQ1" DQA0010A#2 2658.95,361.71 r90 bottom locked (schematic designator U4)
U502 "TPD2E2U06QDCKRQ1" DCK0003A_N 2462.4,373.6 r90 bottom locked (schematic designator U3)
Y1 "AM16070006" FP-AM16070006_SMT_XTAL_3MM2_2MM5-MFG 2614.17,813.46 r90 top locked
ZZ1 "These assemblies are ESD sensitive, ESD precautions shall be observed." AssemblyNote 99.54,2453.25 r0 top locked (schematic designator ZZ2)
ZZ2 "These assemblies must be clean and free from flux and all contaminants. Use of no clean flux is not acceptable." AssemblyNote 99.54,2364.69 r0 top locked (schematic designator ZZ3)
ZZ3 "These assemblies must comply with workmanship standards IPC-A-610 Class 2, unless otherwise specified." AssemblyNote 99.54,2276.14 r0 top locked (schematic designator ZZ4)

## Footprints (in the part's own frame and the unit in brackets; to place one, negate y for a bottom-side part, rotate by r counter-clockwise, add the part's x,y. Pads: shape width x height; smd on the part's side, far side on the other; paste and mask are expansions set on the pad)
0402 [mm] "0402 from SM-752 data"
  rect 0.8x0.6 smd: 1(-0.6,0) 2(0.6,0)
  silkscreen extent -1.22,-0.52 1.22,0.52, body extent -0.55,-0.3 0.55,0.3, height 0.6
0603 [mm] "0603 from SM-752 data"
  rect 1x0.95 smd: 1(-0.8,0) 2(0.8,0)
  silkscreen extent -1.52,-0.69 1.52,0.69, body extent -0.87,-0.47 0.87,0.47, height 1
0805_HV [mil] "0805 with 30mil clearance between pads"
  rect 50x63 smd: 1(-40,0) 2(40,0)
  silkscreen extent -74,-40 74,40, body extent -43,-29 43,29, height 57
1206 [mm] "1206 from SM-752 data"
  rect 1.3x1.85 smd: 1(-1.45,0) 2(1.45,0)
  silkscreen extent -2.4,-1.21 2.4,1.21, body extent -1.7,-0.9 1.7,0.9, height 1.35
1206_180 [mm] "1206_180"
  rect 1.1x1.6 smd: 1(-1.7,0) 2(1.7,0)
  silkscreen extent -0.9,-1 0.9,1, body extent -1.75,-0.95 1.75,0.95, height 1.8
1210_270 [mm] "1210"
  rect 1.3x2.7 smd: 1(-1.45,0) 2(1.45,0)
  silkscreen extent -2.32,-1.57 2.32,1.57, body extent -1.7,-1.35 1.7,1.35, height 2.7
1812_280 [mm] "1812"
  rect 1.6x3.4 smd: 1(-2,0) 2(2,0)
  silkscreen extent -0.8,-1.6 0.8,1.6, body extent -2.4,-1.7 2.4,1.7, height 2.8
AssemblyNote [mil] "Assembly Note"
CAPSMT_62_F55 [mm] "6.3 x 5.2mm:  Chemi-Con F55"
  rect 3.5x1.6 smd: 1(-2.7,0) 2(2.7,0)
  silkscreen extent -3.36,-3.4 3.44,3.4, body extent -3.4,-3.4 3.44,3.4, height 5.5
CAPSMT_62_HA0 [mm] "8 x 10mm:  Chemi-Con HA0"
  rect 4.2x2.2 smd: 1(-3.65,0) 2(3.65,0)
  silkscreen extent -4.25,-4.25 4.25,4.25, body extent -4.25,-4.25 4.25,4.25, height 10.5
CE_Mark_5mm [mil] "Minimum text height for CE Mark"
  silkscreen extent -138,-98 138,98
DBV0005A_N [mm] "SOT23, 5-Leads, Body 2.9x1.6mm, Pitch 0.95mm, Lead Span 2.8mm, IPC Medium Density"
  rrect17% 1x0.6 smd: 1(-1.375,0.95) 2(-1.375,0) 3(-1.375,-0.95) 4(1.375,-0.95) 5(1.375,0.95)
  silkscreen extent -1.62,-1.55 0.38,1.55, body extent -1.42,-1.46 1.42,1.46, height 1.09
DCK0003A_N [mm] "SOT23, 3-Leads, Body 2.0x1.25mm, Pitch 0.65mm, Lead Span 2.1mm, IPC Medium Density"
  rrect25% 0.85x0.4 smd: 1(-1.125,0.65) 2(-1.125,-0.65) 3(1.125,0)
  silkscreen extent -1.02,-1.1 0.7,1.53, body extent -1.06,-1 1.06,1, height 1.1
DGK0008A_L [mm] "TSOP, 8-Leads, Body 3x3mm, Pitch 0.65mm, IPC High Density"
  oval 1.15x0.45 smd: 1(-2.125,0.975) 2(-2.125,0.325) 3(-2.125,-0.325) 4(-2.125,-0.975) 5(2.125,-0.975) 6(2.125,-0.325) 7(2.125,0.325) 8(2.125,0.975)
  silkscreen extent -2.58,-1.55 0.95,1.55, body extent -2.45,-1.5 2.45,1.5, height 0.96
DGK0008A_N [mm] "TSOP, 8-Leads, Body 3x3mm, Pitch 0.65mm, IPC Medium Density"
  oval 1.35x0.45 smd: 1(-2.225,0.975) 2(-2.225,0.325) 3(-2.225,-0.325) 4(-2.225,-0.975) 5(2.225,-0.975) 6(2.225,-0.325) 7(2.225,0.325) 8(2.225,0.975)
  silkscreen extent -2.75,-1.55 0.95,1.55, body extent -2.45,-1.5 2.45,1.5, height 0.96
DQA0010A#1 [mm] "SON, 10-Leads, Body 1x2.5mm, Pitch 0.5mm, TI Recommended"
  rrect50% 0.565x0.2 smd: 1(-0.417,1) 2(-0.417,0.5) 4(-0.417,-0.5) 5(-0.417,-1) 6(0.418,-1) 7(0.418,-0.5) 9(0.417,0.5) 10(0.417,1)
  rrect25% 0.565x0.4 smd paste-0.2: 3(-0.417,0) 8(0.417,0)
  rrect28% 0.565x0.36 on Top Paste: 3(-0.417,0) 8(0.418,0)
  silkscreen extent -0.68,-1.45 0.55,1.45, body extent -0.55,-1.3 0.55,1.3, height 0.56
DQA0010A#2 [mm] "SON, 10-Leads, Body 1x2.5mm, Pitch 0.5mm, TI Recommended"
  rrect50% 0.565x0.2 smd: 1(-0.417,1) 2(-0.417,0.5) 4(-0.417,-0.5) 5(-0.417,-1) 6(0.418,-1) 7(0.418,-0.5) 9(0.418,0.5) 10(0.417,1)
  rrect28% 0.565x0.36 on Bottom Paste: 3(-0.417,0) 8(0.418,0)
  rrect25% 0.565x0.4 smd paste-0.2: 3(-0.417,0) 8(0.418,0)
  silkscreen extent -0.68,-1.45 0.55,1.45, body extent -0.55,-1.3 0.55,1.3, height 0.56
DQK0006C [mm] "WSON"
  rrect12% 0.9x0.86 on Top Paste: 0(0,0.325)
  rrect34% 0.7x0.29 on Top Paste: 0(0.095,-0.65)
  rrect33% 0.45x0.3 smd: 1(-0.975,0.65) 2(-0.975,0) 3(-0.975,-0.65) 4(0.975,-0.65) 5(0.975,0) 6(0.975,0.65)
  rrect33% 0.75x0.3 smd paste-0.15: 7(0.095,-0.65)
  rrect11% 1x0.95 smd paste-0.5: 8(0,0.325)
  silkscreen extent -1.15,-1.15 1.15,1.15, body extent -1,-1 1,1, height 0.82
DRC0010J [mm] "VSON-10"
  rrect42% 0.6x0.24 smd: 1(-1.4,1) 2(-1.4,0.5) 3(-1.4,0) 4(-1.4,-0.5) 5(-1.4,-1) 6(1.4,-1) 7(1.4,-0.5) 8(1.4,0) 9(1.4,0.5) 10(1.4,1)
  rrect12% 1.65x2.4 smd paste-1 mask-2: 11(0,0)
  Top Layer region: -0.375,-1.65 -0.375,-1.2 -0.775,-1.2 -0.794,-1.196 -0.81,-1.185 -0.821,-1.169 -0.825,-1.15 -0.825,-1.15 -0.825,1.15 -0.821,1.169 -0.81,1.185 -0.794,1.196 -0.775,1.2 -0.775,1.2 -0.375,1.2 -0.375,1.65 -0.371,1.669 -0.36,1.685 -0.344,1.696 -0.325,1.7 -0.325,1.7 -0.325,1.7 -0.175,1.7 -0.175,1.7 -0.156,1.696 -0.14,1.685 -0.129,1.669 -0.125,1.65 -0.125,1.65 -0.125,1.2 0.125,1.2 0.125,1.65 0.129,1.669 0.14,1.685 0.156,1.696 0.175,1.7 0.175,1.7 0.175,1.7 0.325,1.7 0.325,1.7 0.344,1.696 0.36,1.685 0.371,1.669 0.375,1.65 0.375,1.65 0.375,1.2 0.775,1.2 0.794,1.196 0.81,1.185 0.821,1.169 0.825,1.15 0.825,1.15 0.825,-1.15 0.821,-1.169 0.81,-1.185 0.794,-1.196 0.775,-1.2 0.775,-1.2 0.375,-1.2 0.375,-1.65 0.371,-1.669 0.36,-1.685 0.344,-1.696 0.325,-1.7 0.325,-1.7 0.175,-1.7 0.156,-1.696 0.14,-1.685 0.129,-1.669 0.125,-1.65 0.125,-1.65 0.125,-1.2 -0.125,-1.2 -0.125,-1.65 -0.129,-1.669 -0.14,-1.685 -0.156,-1.696 -0.175,-1.7 -0.175,-1.7 -0.325,-1.7 -0.344,-1.696 -0.36,-1.685 -0.371,-1.669 -0.375,-1.65
  body extent -1.5,-1.5 1.5,1.5, height 1
DRV0006A [mm] "SON, 6-Leads, Body 2x2mm, Pitch 0.65mm, Thermal Pad 1.6x1mm, TI Recommended"
  rrect33% 0.45x0.3 smd: 1(-0.975,0.65) 2(-0.975,0) 3(-0.975,-0.65) 4(0.975,-0.65) 5(0.975,0) 6(0.975,0.65)
  rrect10% 1x1.6 smd paste-0.5: 7(0,0)
  rrect14% 1x0.7 on Top Paste: 7(0,-0.45) 7(0,0.45)
  silkscreen extent -1.05,-1.2 1.05,1.2, body extent -1.05,-1.05 1.05,1.05, height 0.81
FCC_disclaimer [mil]
FDSD0420 [mm] "SMD, 2-Leads, Body 4.2x4.2mm"
  rect 1.4x2.4 smd: 1(-1.6,0) 2(1.6,0)
  silkscreen extent -2.2,-2.2 2.2,2.2, body extent -2.1,-2.1 2.1,2.1, height 2
Fiducial10-20 [mm]
  round 1 smd mask+0.5: 1(0,0)
  Top Layer keep-out circle w1.178: c0,0 r0.5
